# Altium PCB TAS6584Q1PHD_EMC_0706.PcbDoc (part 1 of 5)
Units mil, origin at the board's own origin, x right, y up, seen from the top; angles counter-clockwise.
Board outline 7086.61 x 5118.11 mil, 6 copper layers (Top Layer, GND02, SIG03, SIG04, GND05, Bottom Layer), stack 60.484 mil thick; 461 components, 247 nets, 1337 pads, 1658 vias.
Unrouted connection lines stored in the file: 67.
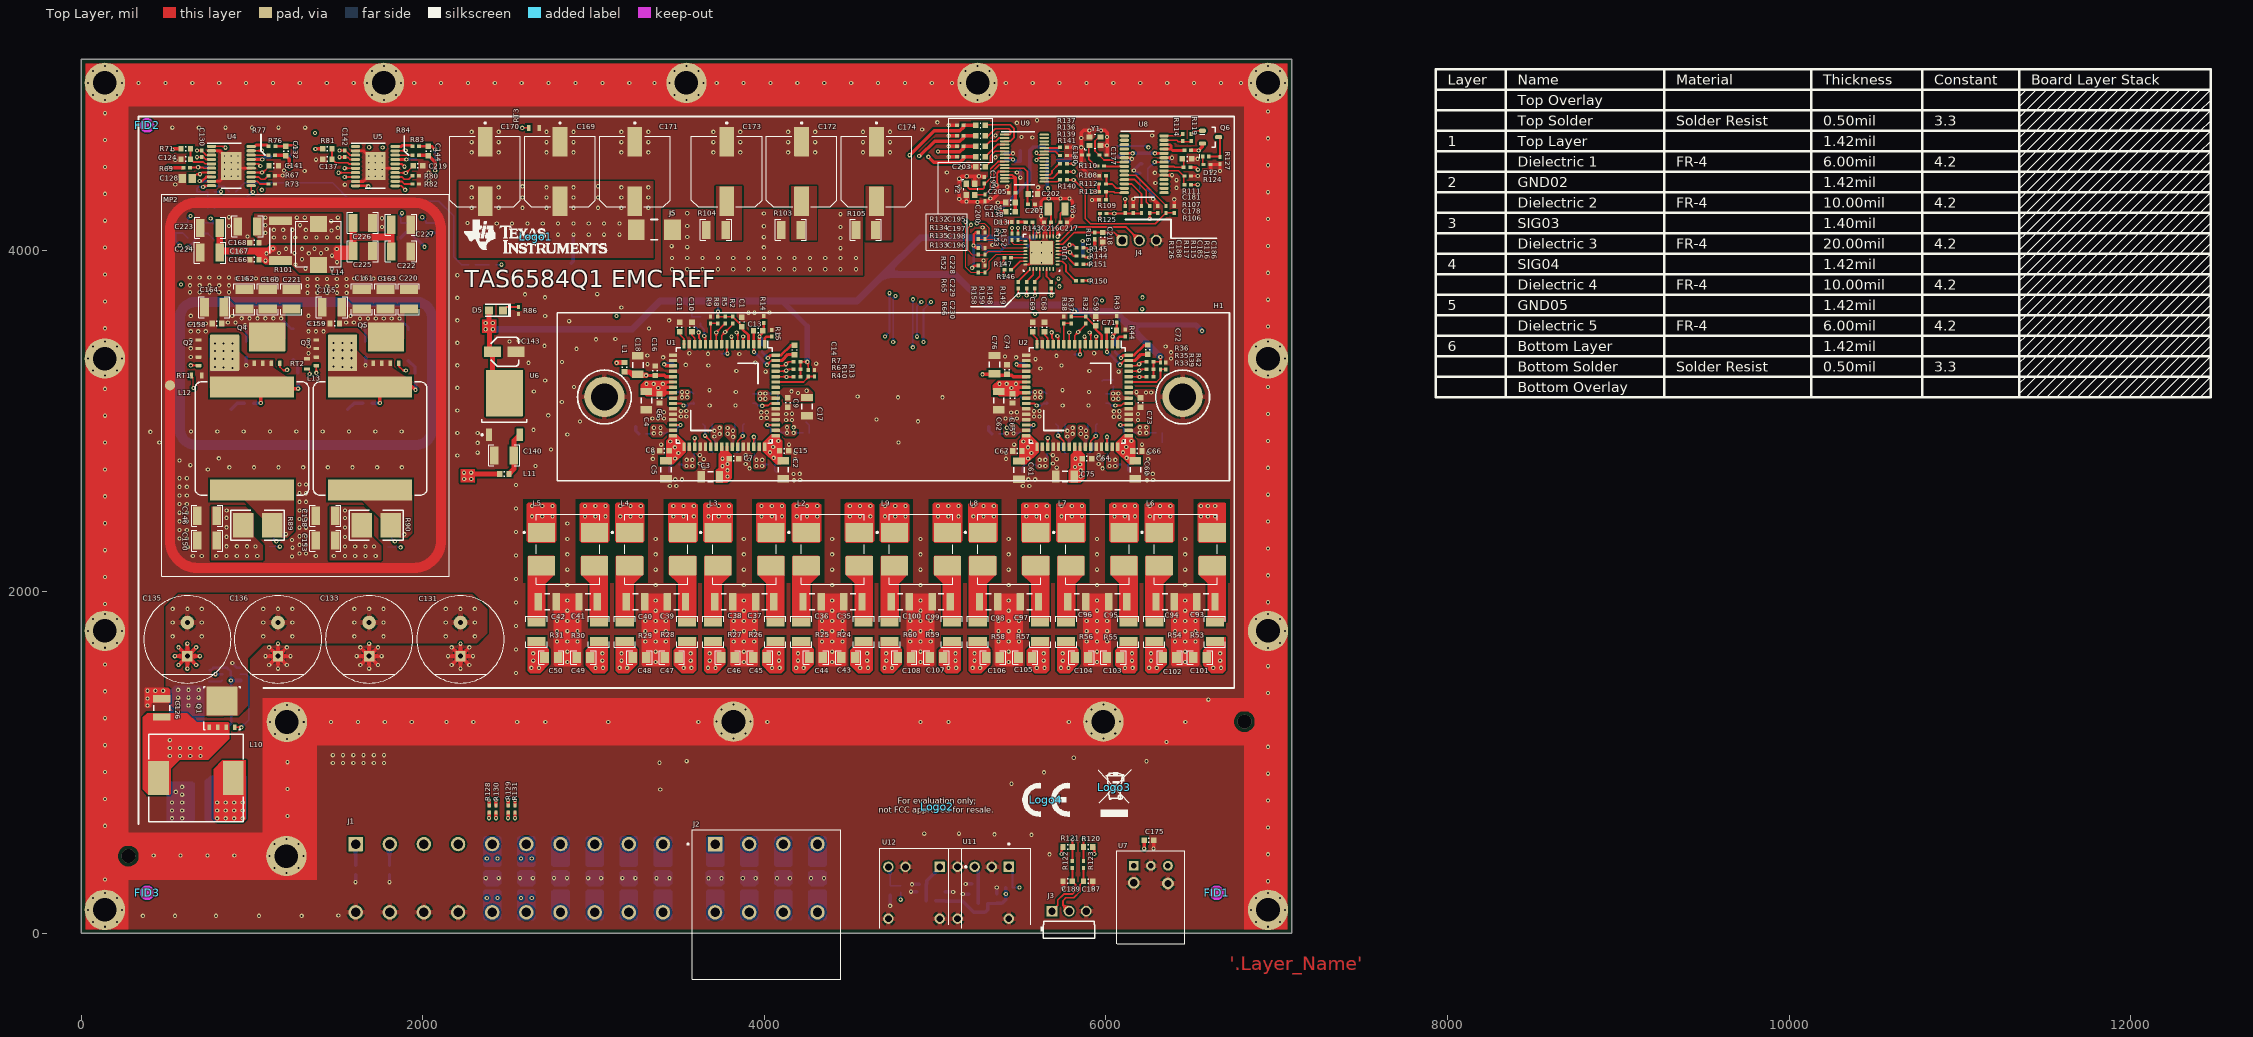
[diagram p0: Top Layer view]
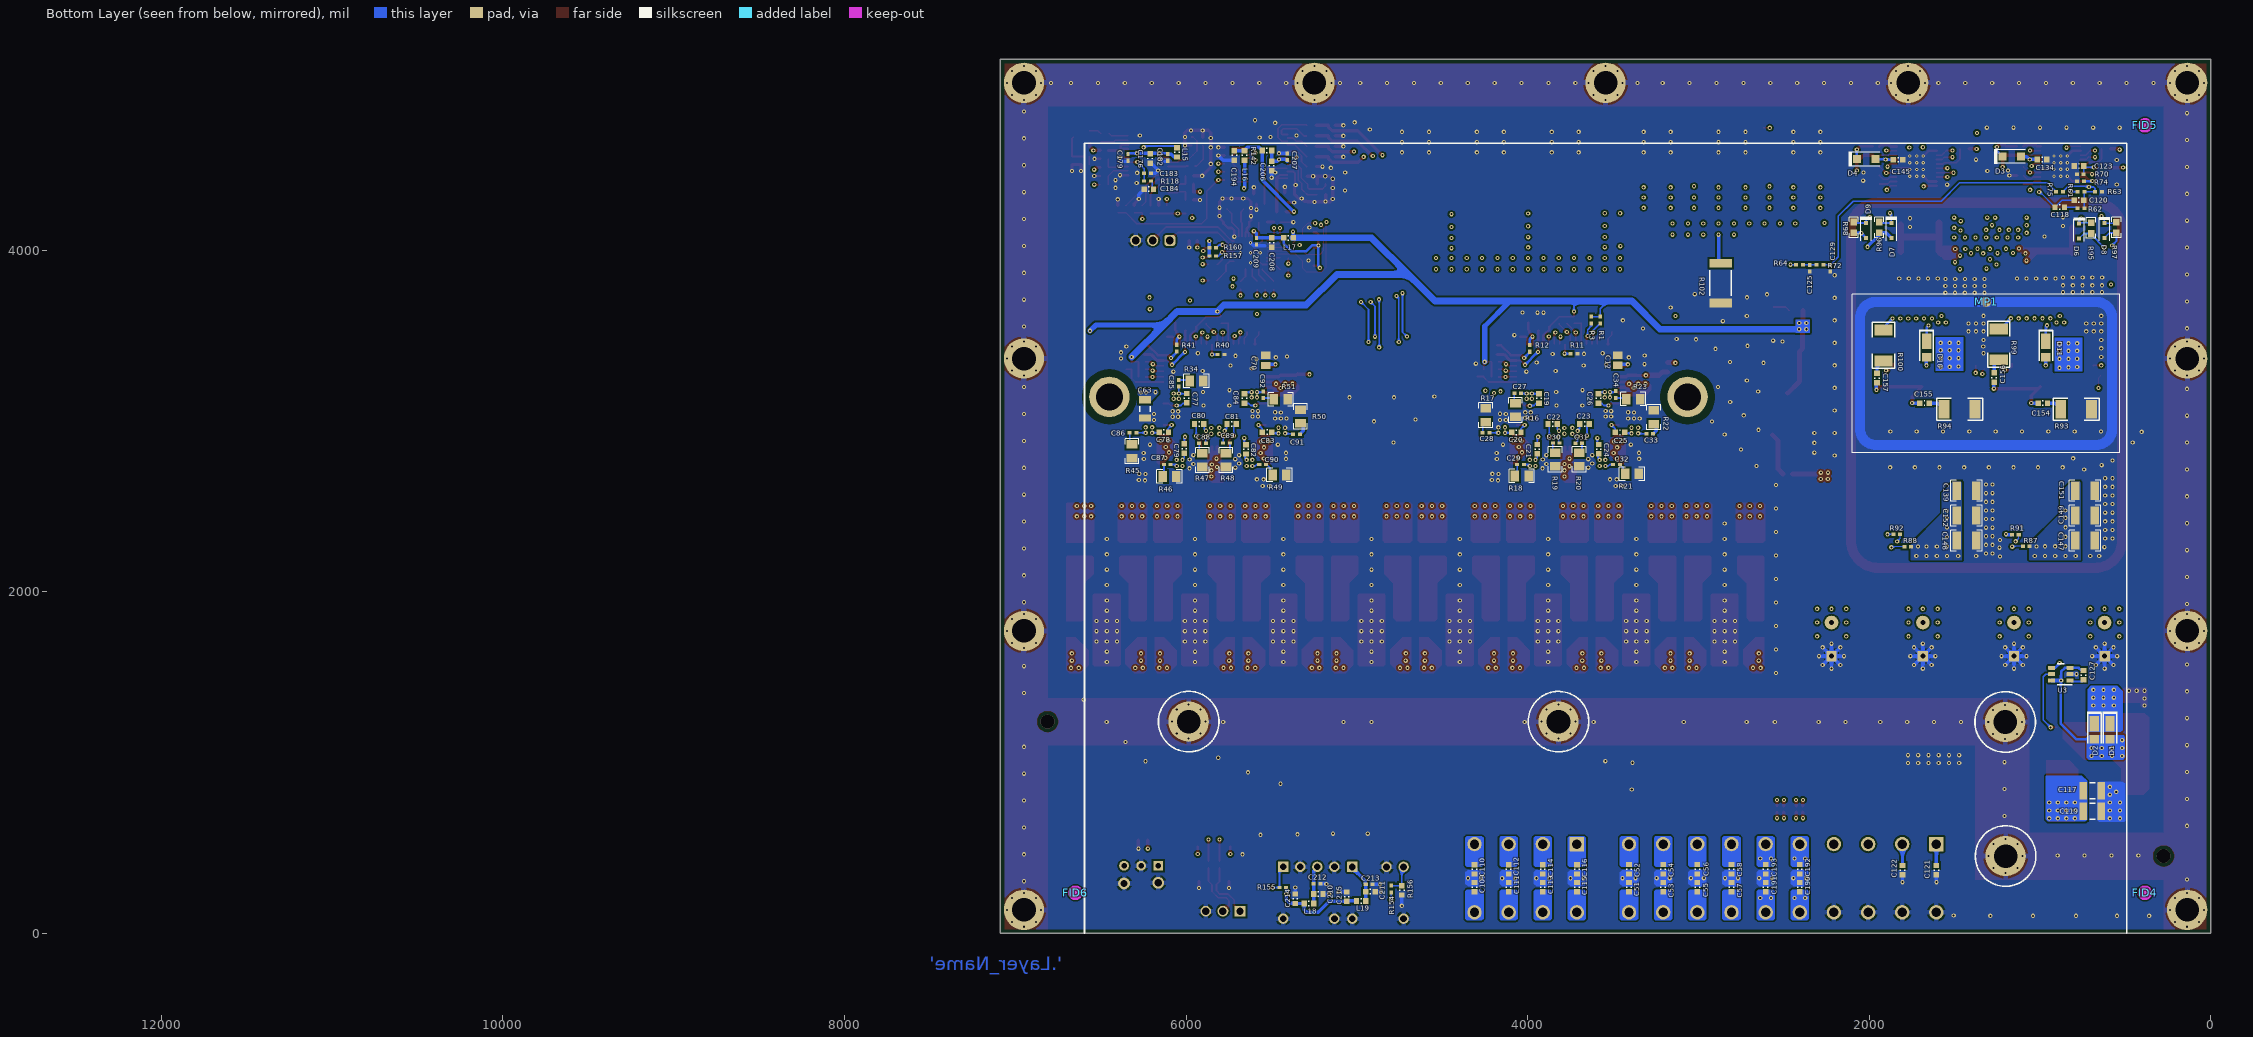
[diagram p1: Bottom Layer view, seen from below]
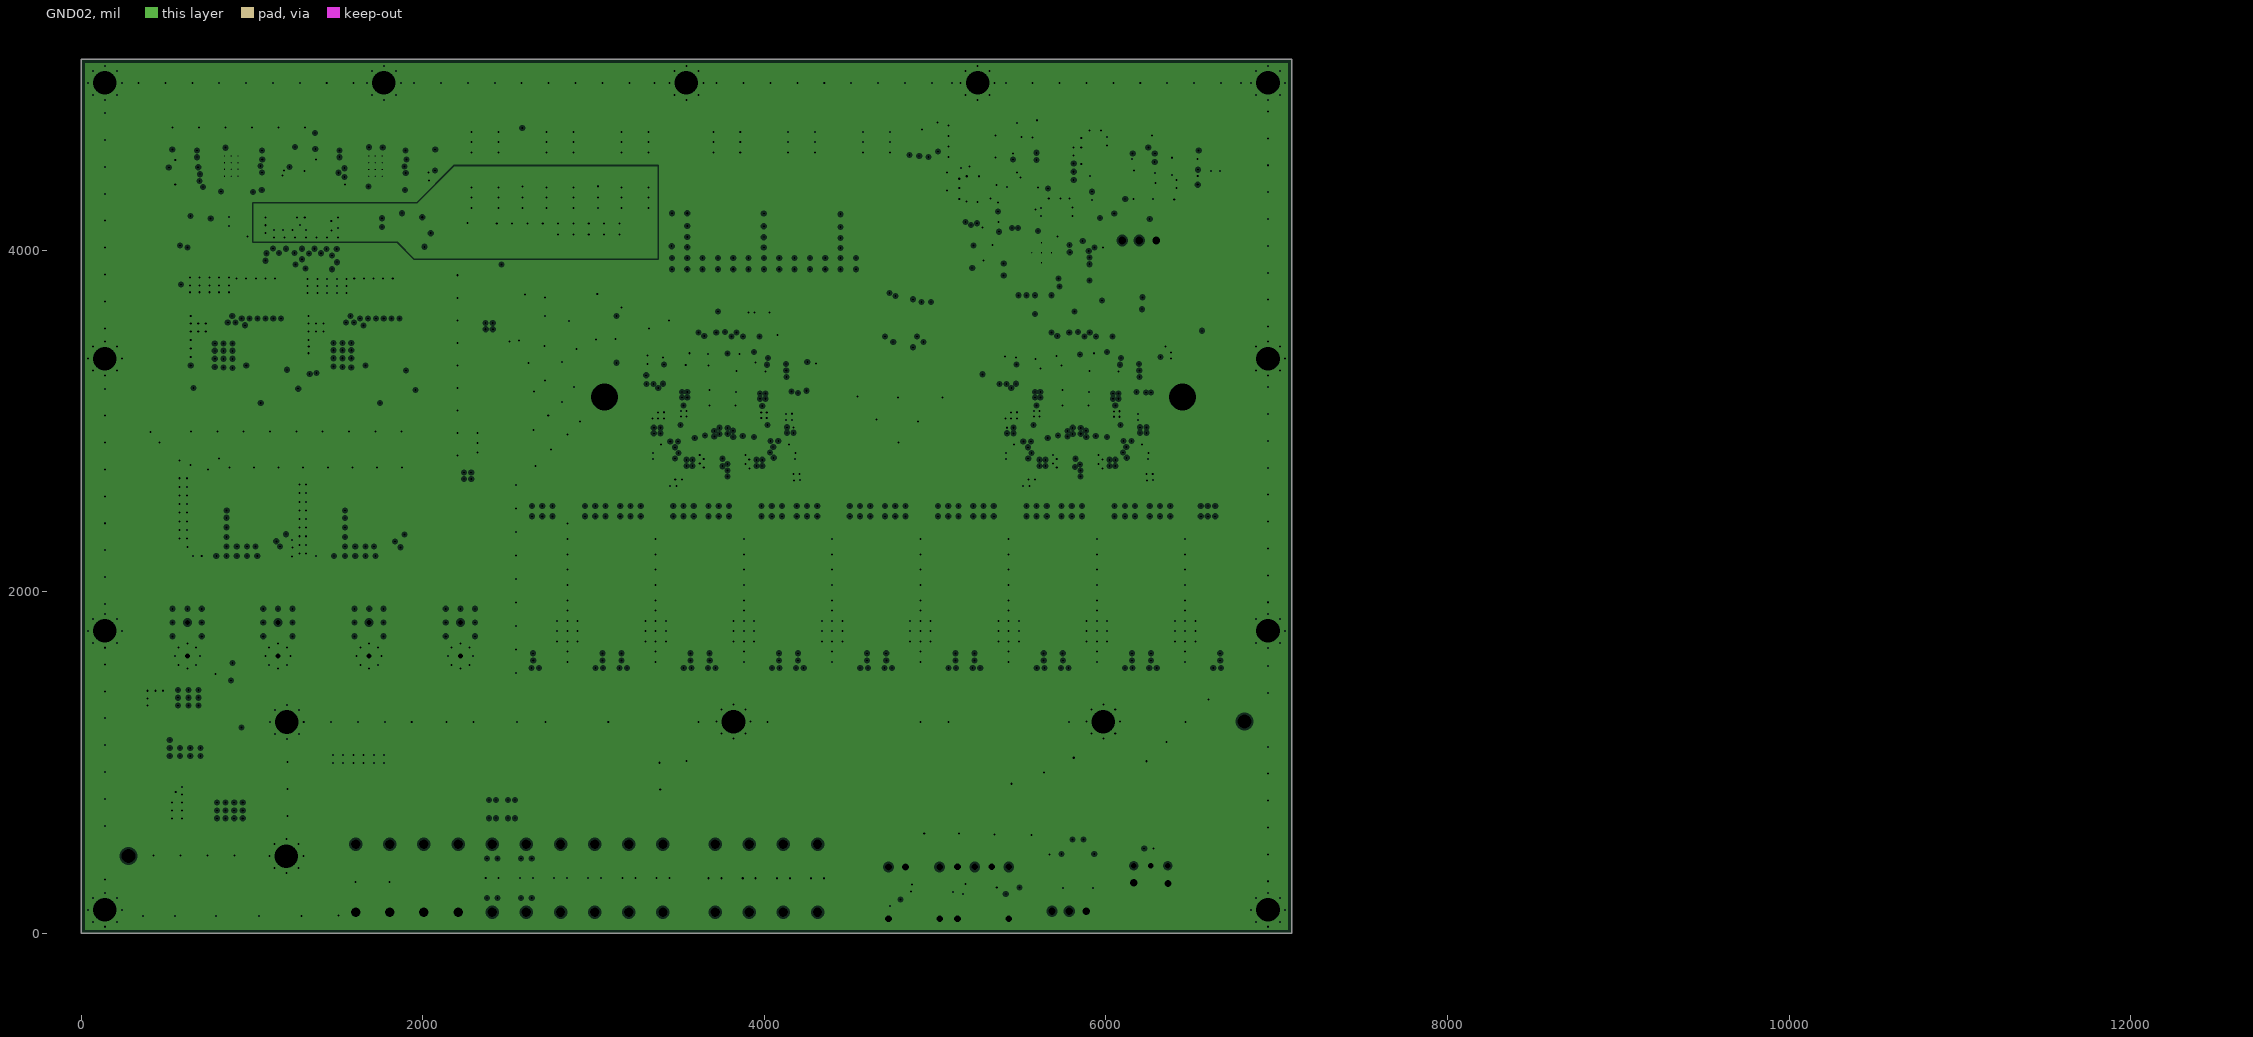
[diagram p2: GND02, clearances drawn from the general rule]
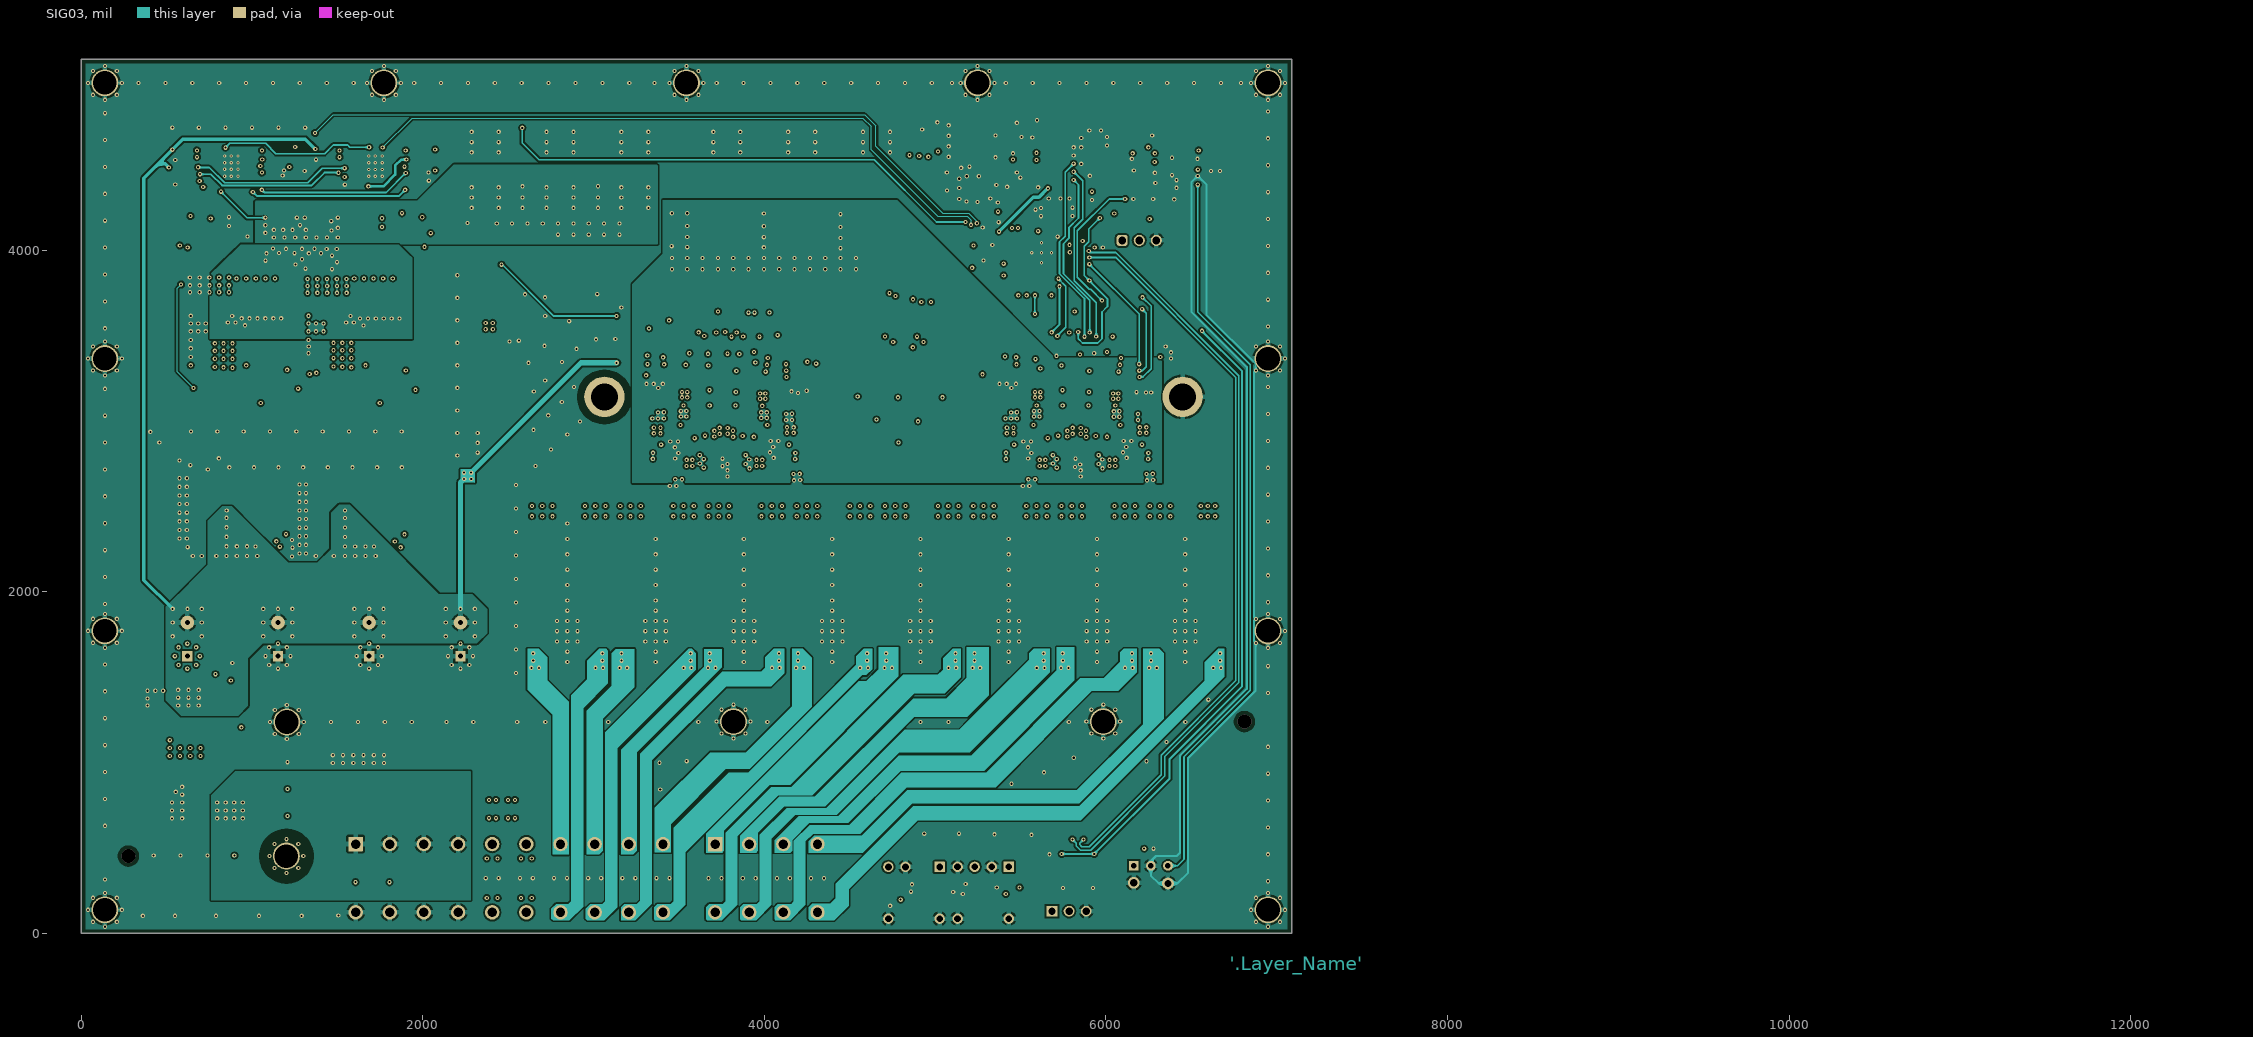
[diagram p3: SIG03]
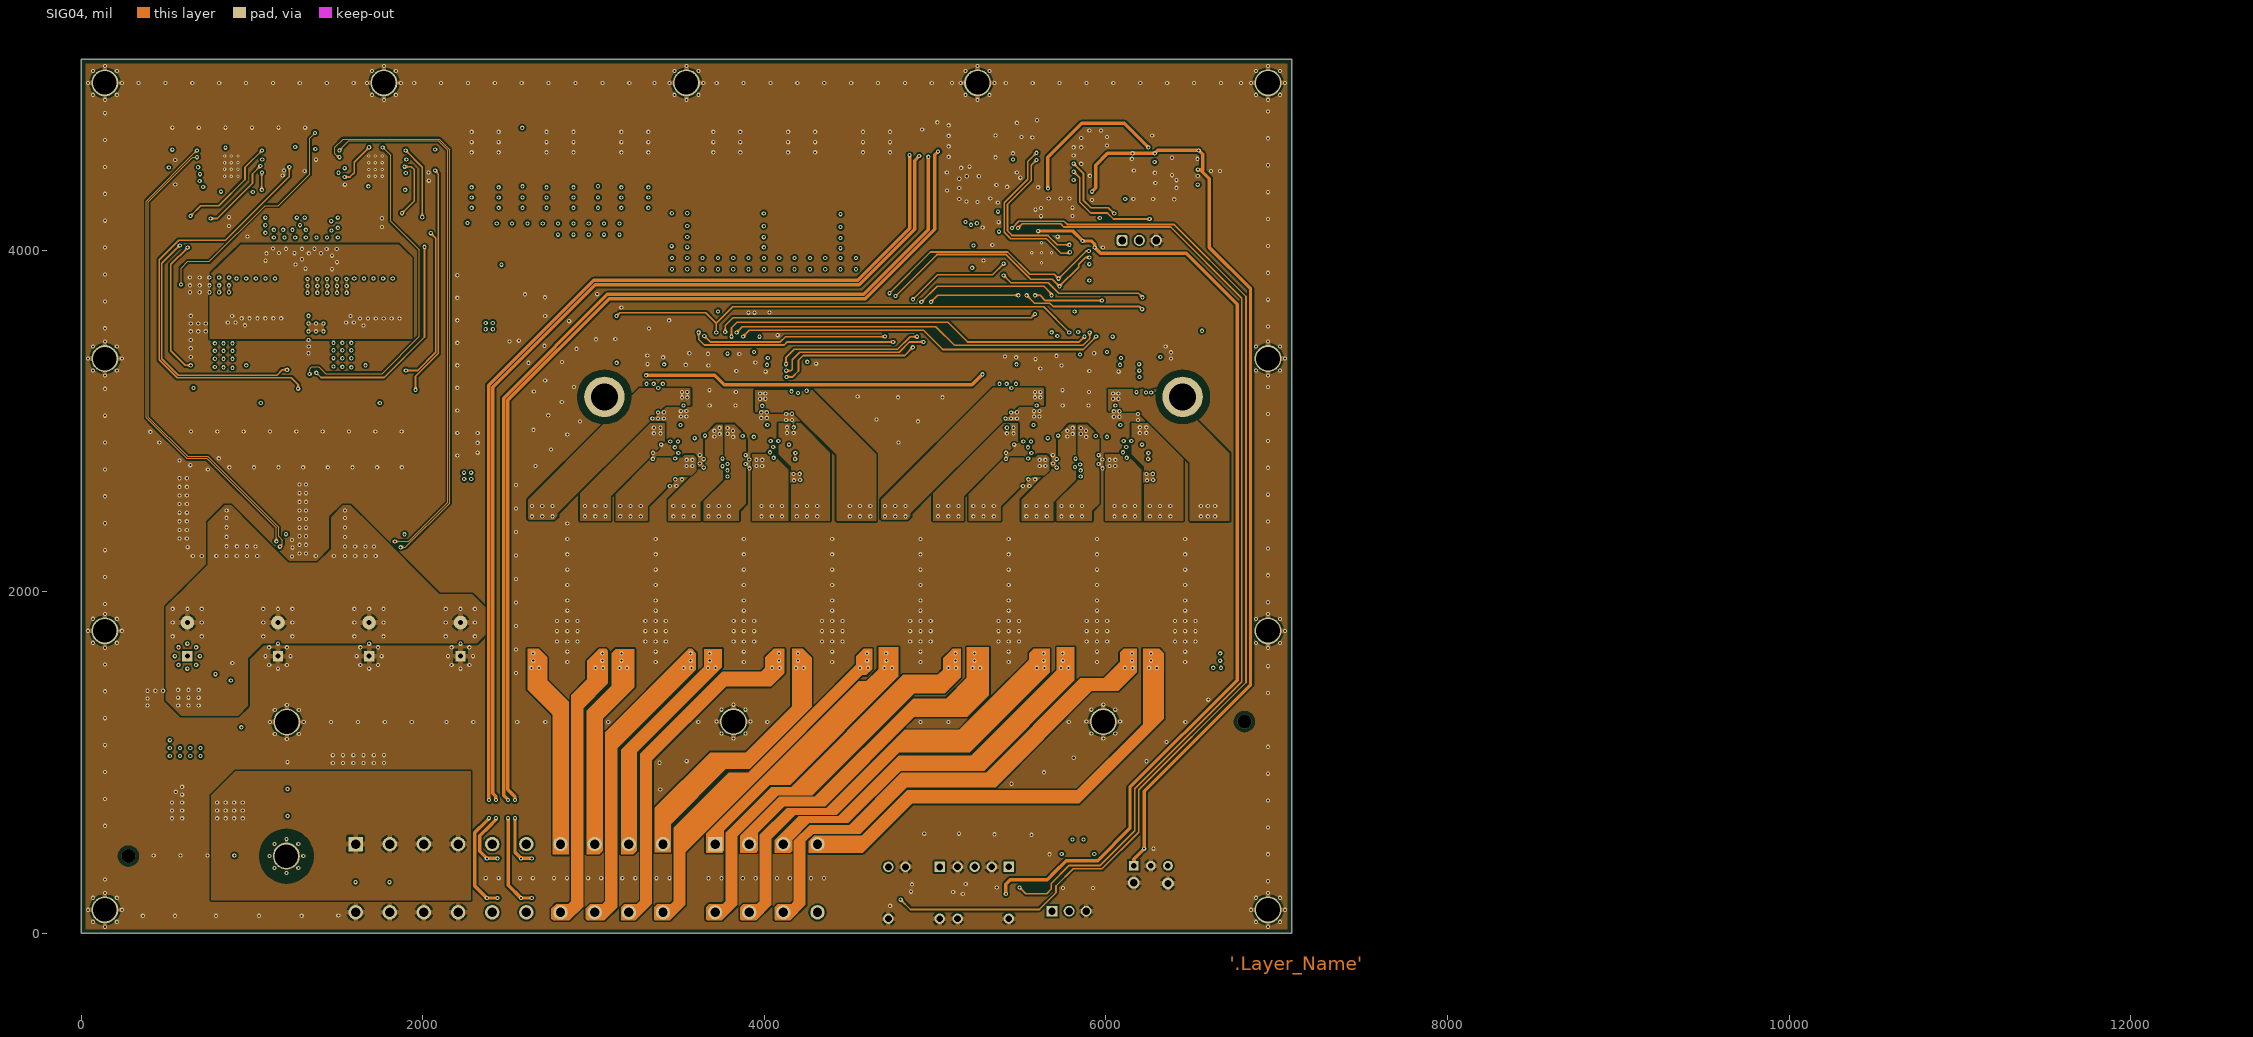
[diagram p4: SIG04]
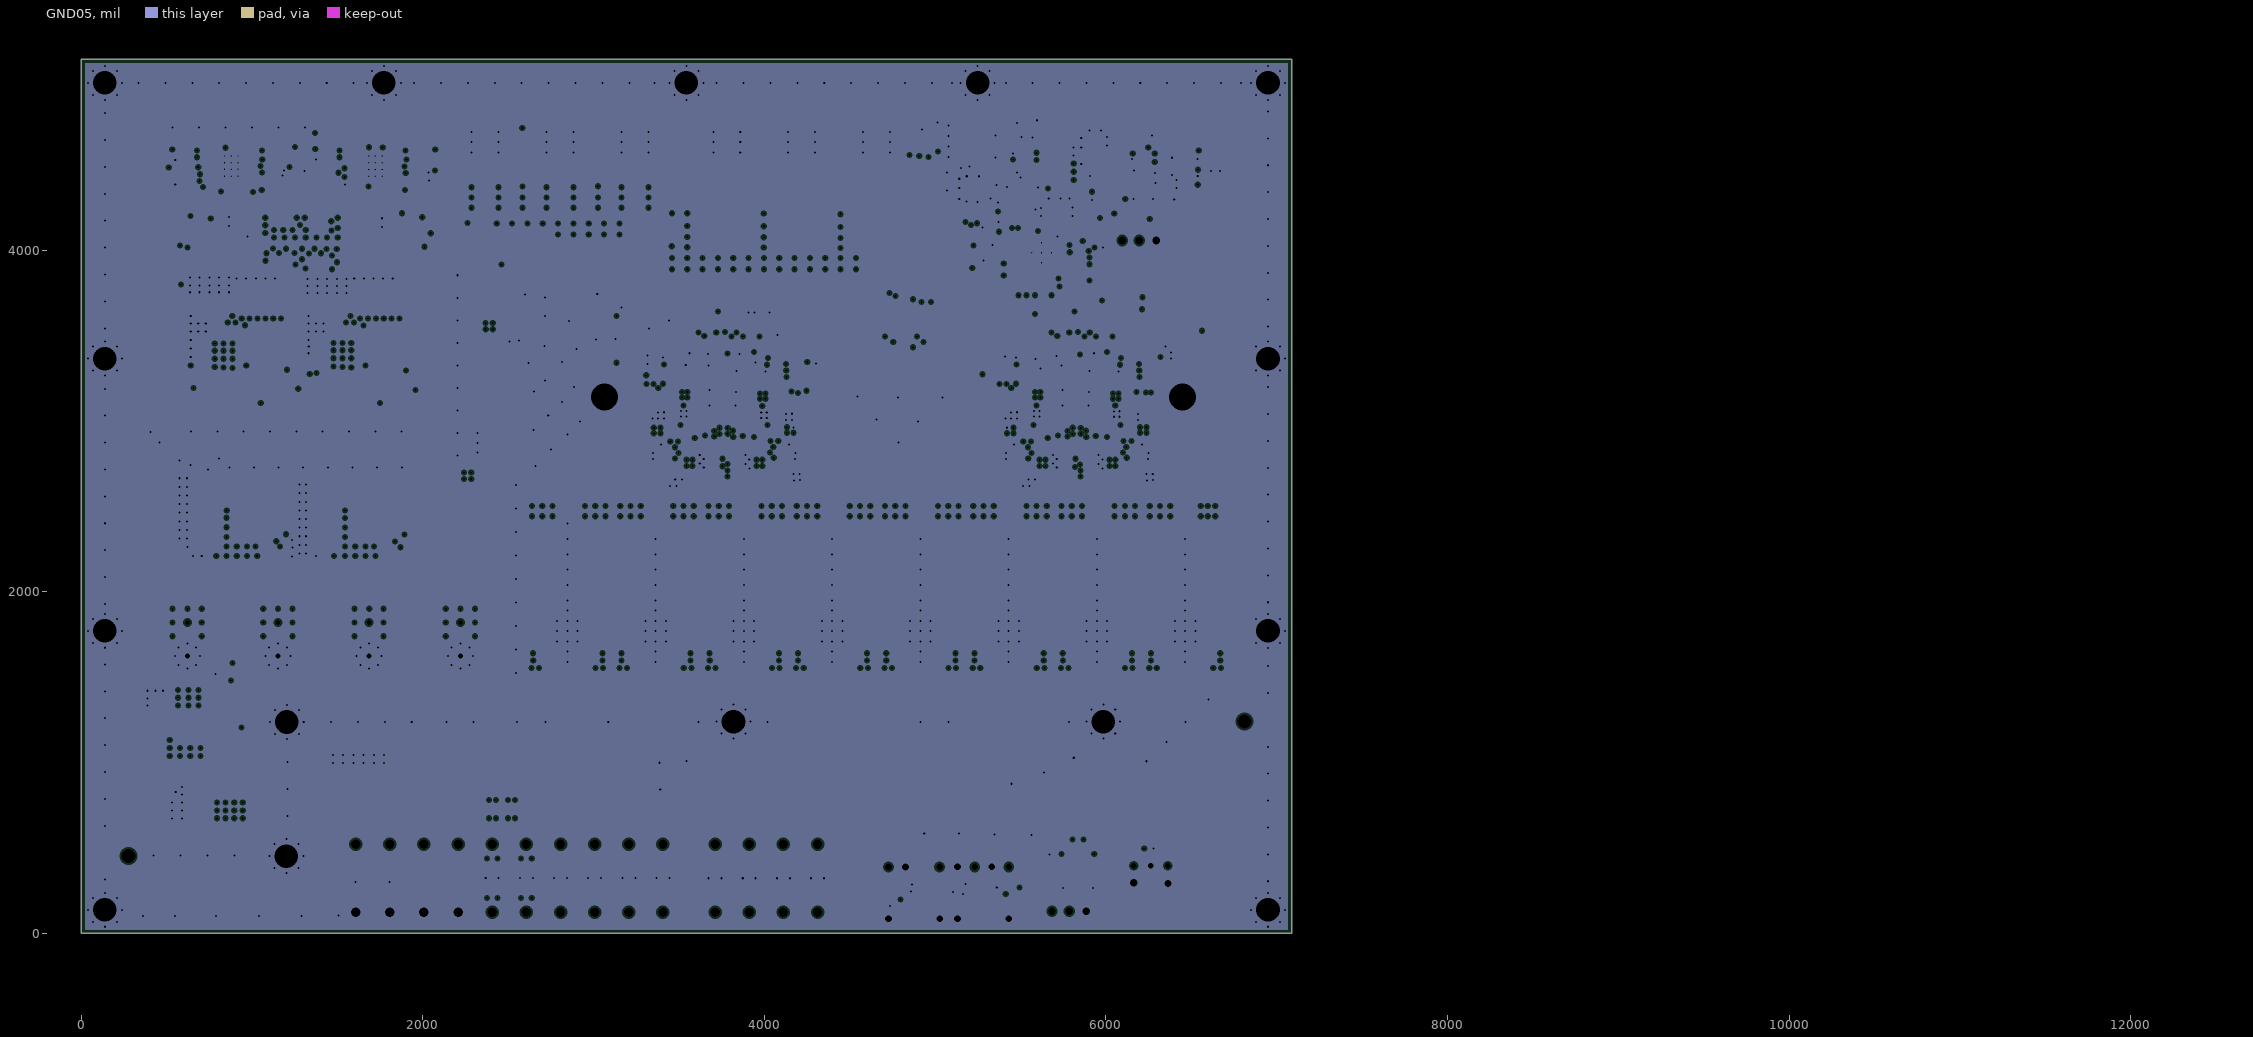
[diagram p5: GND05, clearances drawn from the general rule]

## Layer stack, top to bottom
Top Solder: solder mask 0.5, Solder Resist, Dk 3.3
Top Layer: signal copper 1.4169
Dielectric 1: prepreg 6, FR-4, Dk 4.2
GND02: plane copper 1.4169, net (Multiple Nets)
Dielectric 2: prepreg 10, FR-4, Dk 4.2
SIG03: signal copper 1.4
Dielectric 3: core 20, FR-4, Dk 4.2
SIG04: signal copper 1.4169
Dielectric 4: prepreg 10, FR-4, Dk 4.2
GND05: plane copper 1.4169, net GND
Dielectric 5: prepreg 6, FR-4, Dk 4.2
Bottom Layer: signal copper 1.4169
Bottom Solder: solder mask 0.5, Solder Resist, Dk 3.3

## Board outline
0,0 7086.61,0 7086.61,5118.11 0,5118.11

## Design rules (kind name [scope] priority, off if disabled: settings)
AcuteAngle [All] p1 off: minimum=4.50000000000000E+0001 checktracksonly=FALSE
AssemblyTestPointUsage [All] p1 off: valid=2
AssemblyTestpoint [All] p1 off: testpointundercomponent=TRUE minsize=40 maxsize=100 preferedsize=60 minholesize=0 maxholesize=40 preferedholesize=32 testpointgrid=1 usegrid=TRUE gridtolerance=0.01 allowsidetop=TRUE allowsidebottom=TRUE
Clearance Clearance_FID [InComponent('FID*')] p1: gap=7.87 ignorepadtopadclearanceinfootprint=TRUE except(0: Arc-SMDPad Arc-Hole Track-SMDPad Track-Hole SMDPad-Hole THPad-Hole Via-Hole Fill-Hole Poly-Hole Region-Hole Text-Hole; 20: Fill-Fill Fill-Poly Fill-Region Poly-Poly Poly-Region Region-Region)
Clearance [All] p2: gap=10 ignorepadtopadclearanceinfootprint=TRUE except(0: Arc-Text Arc-Hole Track-Text Track-Hole SMDPad-Text SMDPad-Hole THPad-Text THPad-Hole Via-Text Via-Hole Fill-Text Fill-Hole Poly-Text Poly-Hole Region-Text Region-Hole Text-Text Text-Hole; 5: Arc-Arc Arc-Track Track-Track; 7: Arc-SMDPad Arc-THPad Arc-Via Track-SMDPad Track-THPad Track-Via SMDPad-SMDPad SMDPad-THPad SMDPad-Via THPad-THPad THPad-Via Via-Via)
ComponentClearance ComponentClearance_1 [InComponent('H1')] p1: gap=-1000 collisioncheckmode=3 verticalgap=100000 showdistances=FALSE
ComponentClearance ComponentClearance_MountingHoles_FiducialMarks [InComponentClass('Mounting Holes') vs InComponentClass('FiducialMark')] p2: gap=50 collisioncheckmode=3 verticalgap=10 showdistances=FALSE
ComponentClearance ComponentClearance_Shunt [InComponentClass('Header') vs InComponentClass('Shunt')] p3: gap=0 collisioncheckmode=3 verticalgap=0 showdistances=FALSE
ComponentClearance ComponentClearance_Logo [InComponentClass('Logo')] p4: gap=50 collisioncheckmode=3 verticalgap=100000 showdistances=FALSE
ComponentClearance ComponentClearance_ScrewToNut [(HasFootprint('NY PMS 440 0025 PH')) vs (HasFootprint('Keystone_1902C'))] p5: gap=5 collisioncheckmode=3 verticalgap=10 showdistances=FALSE
ComponentClearance ComponentClearance_MountingHoles [InComponentClass('Mounting Holes')] p6: gap=250 collisioncheckmode=3 verticalgap=100000 showdistances=FALSE
ComponentClearance ComponentClearance_SmallPassives [HasFootprint('0201*') or HasFootprint('0402*') or HasFootprint('0508') or HasFootprint('0603*') or HasFootprint('0612') or HasFootprint('0805*') or HasFootprint('0815*') or HasFootprint('0830*') or HasFootprint('1206*') or HasFootprint('1210*') or HasFootprint('1808*') or HasFootprint('1812*') or HasFootprint('1825*') or HasFootprint('2010*') or HasFootprint('2220*') or HasFootprint('2225*') or HasFootprint('2512*') or HasFootprint('2728*') or HasFootprint('3518*') vs HasFootprint('0201*') or HasFootprint('0402*') or HasFootprint('0508') or HasFootprint('0603*') or HasFootprint('0612') or HasFootprint('0805*') or HasFootprint('0815*') or HasFootprint('0830*') or HasFootprint('1206*') or HasFootprint('1210*') or HasFootprint('1808*') or HasFootprint('1812*') or HasFootprint('1825*') or HasFootprint('2010*') or HasFootprint('2220*') or HasFootprint('2225*') or HasFootprint('2512*') or HasFootprint('2728*') or HasFootprint('3518*')] p7: gap=14.96 collisioncheckmode=3 verticalgap=10 showdistances=FALSE
ComponentClearance ComponentClearance_THtoSMT [IsThruComponent vs IsSMTComponent] p8: gap=40 collisioncheckmode=3 verticalgap=25 showdistances=FALSE
ComponentClearance ComponentClearance_THtoTH [IsThruComponent vs IsThruComponent] p9: gap=20 collisioncheckmode=3 verticalgap=20 showdistances=FALSE
ComponentClearance [All] p10: gap=5 collisioncheckmode=3 verticalgap=5 showdistances=FALSE
DiffPairsRouting [All] p1 off: maxlimit=100 minlimit=10 mostfreqgap=10 toplayer_minwidth=15 toplayer_maxwidth=15 toplayer_prefwidth=15 midlayer3_minwidth=15 midlayer3_maxwidth=15 midlayer3_prefwidth=15 midlayer6_minwidth=15 midlayer6_maxwidth=15 midlayer6_prefwidth=15 bottomlayer_minwidth=15 bottomlayer_maxwidth=15 bottomlayer_prefwidth=15 maxuncoupledlength=1000
FabricationTestPointUsage TestPointUsage [All] p1 off: valid=2 allowmultiple=FALSE
FabricationTestpoint Testpoint [All] p1 off: side=3 testpointundercomponent=TRUE minsize=40 maxsize=100 preferedsize=60 minholesize=0 maxholesize=40 preferedholesize=32 testpointgrid=1 allowsidetop=TRUE allowsidebottom=TRUE usegrid=TRUE gridtolerance=0.01
FanoutControl Fanout_LCC [IsLCC] p1 off: bgadir=Out bgaviamode=Centered fanoutstyle=Auto fanoutdirection=Alternating viagrid=1 // Fanout_LCC (Default Rule)
FanoutControl Fanout_BGA [IsBGA] p2 off: bgadir=Out bgaviamode=Centered fanoutstyle=Auto fanoutdirection=Alternating viagrid=1 // Fanout_BGA (Default Rule)
FanoutControl Fanout_SOIC [IsSOIC] p3 off: bgadir=Out bgaviamode=Centered fanoutstyle=Auto fanoutdirection=Alternating viagrid=1 // Fanout_SOIC (Default Rule)
FanoutControl Fanout_Default [All] p4 off: bgadir=Out bgaviamode=Centered fanoutstyle=Auto fanoutdirection=Alternating viagrid=1 // Fanout_Default (Default Rule)
FanoutControl Fanout_Small [(CompPinCount < 5)] p5 off: bgadir=Out bgaviamode=Centered fanoutstyle=Auto fanoutdirection=OutThenIn viagrid=1 // Fanout_Small (Default Rule)
Height [All] p1 off: minheight=0 maxheight=1000 prefheight=500
HoleSize [All] p1 off: absolutevalues=TRUE maxlimit=251 minlimit=7.87 maxpercent=80.000 minpercent=20.000
HoleToHoleClearance [All] p1 off: gap=10 allowstackedmicrovias=TRUE
LayerPairs [All] p1 off: enforce=TRUE
MinimumAnnularRing MinimumAnnularRing_ThermalPadVias [IsVia and InAnyComponent] p1 off: minimumring=5.91
MinimumAnnularRing [All] p2 off: minimumring=7.87
MinimumSolderMaskSliver MinimumSolderMaskSliver_Logo [InComponentClass('Logo') vs InComponentClass('Logo')] p1 off: minsoldermaskwidth=0.7
MinimumSolderMaskSliver [All] p2 off: minsoldermaskwidth=3.94
PlaneClearance [All] p1: clearance=12
PlaneConnect PlaneConnect_1 [IsThruPin] p1: planeconnectstyle=Relief reliefexpansion=10 reliefentries=4 reliefconductorwidth=30 reliefairgap=12
PlaneConnect [All] p2: planeconnectstyle=Direct reliefexpansion=10 reliefentries=4 reliefconductorwidth=10 reliefairgap=10
PolygonConnect PolygonConnect_1 [IsThruPin] p1: connectstyle=Relief reliefconductorwidth=30 reliefentries=4 polygonreliefangle="90 Angle" airgapwidth=12
PolygonConnect [All] p2: connectstyle=Direct reliefconductorwidth=20 reliefentries=4 polygonreliefangle="90 Angle" airgapwidth=12
RoutingVias [All] p1: holewidth=12 width=25 viastyle="Through Hole" minholewidth=10 minwidth=20 maxholewidth=15 maxwidth=30 useviatemplates=TRUE viatemplateguid#1={6C5415AD-AB15-4F71-99E7-3C6550FFFBAB} viatemplatename#1=v64h30
SilkToBoardRegionClearance [Not ((IsComment or IsDesignator) And (Hide <> 'False')) and not InRegion(1000,500,4000,800)] p1 off:
SilkToSilkClearance SilkToSilkClearance_Pb-FreeLogo [(HasFootprint('Pb-Free_Overlay_Medium') OR HasFootprint('Pb-Free_Overlay_Small')) vs (HasFootprint('Pb-Free_Overlay_Medium') OR HasFootprint('Pb-Free_Overlay_Small'))] p1 off: silktosilkclearance=0
SilkToSilkClearance [All] p2 off: silktosilkclearance=3.94
SilkToSolderMaskClearance SilkToComponentPadClearance [(IsPad or IsFill or IsRegion) and InAnycomponent] p1 off: minsilkscreentomaskgap=5 clearancetoexposedcopper=TRUE
SilkToSolderMaskClearance "Silk to Solder Mask Opening" [All] p2 off: minsilkscreentomaskgap=3.94 clearancetoexposedcopper=FALSE
SolderMaskExpansion SolderMaskExpansion_1 [isvia] p1: expansion=-40 istentingtop=FALSE
SolderMaskExpansion [All] p2: expansion=1.97 istentingtop=FALSE
ViasUnderSMD [All] p1 off: allowed=FALSE
Width Width_1 [InNetClass('PW')] p1: maxlimit=200 minlimit=10 preferedwidth=16
Width [All] p2: maxlimit=100 minlimit=6 preferedwidth=10 checkconnectedcopper=TRUE
9 further rules are at their usual default settings.

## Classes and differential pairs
component class FiducialMark: FID1 FID2 FID3 FID4 FID5 FID6
component class TAS6584Q1PHD_2: C59 C60 C61 C62 C63 C64 C65 C66 C67 C68 C69 C70 C71 C72 C73 C74 C75 C76 C77 C78 C79 C80 C81 C82 C83 C84 C85 C86 C87 C88 C89 C90 C91 C92 C93 C94 C95 C96 C97 C98 C99 C100 C101 C102 C103 C104 C105 C106 C107 C108 C109 C110 C111 C112 C113 C114 C115 C116 L6 L7 L8 L9 R32 R33 R34 R35 R36 R37 R38 R39 R40 R41 R42 R43 R44 R45 R46 R47 R48 R49 R50 R51 R53 R54 R55 R56 R57 R58 R59 R60 U2
component class TAS6584Q1PHD_1: C1 C2 C3 C4 C5 C6 C7 C8 C9 C10 C11 C12 C13 C14 C15 C16 C17 C18 C19 C20 C21 C22 C23 C24 C25 C26 C27 C28 C29 C30 C31 C32 C33 C34 C35 C36 C37 C38 C39 C40 C41 C42 C43 C44 C45 C46 C47 C48 C49 C50 C51 C52 C53 C54 C55 C56 C57 C58 H1 L1 L2 L3 L4 L5 R1 R2 R3 R4 R5 R6 R7 R8 R9 R10 R11 R12 R13 R14 R15 R16 R17 R18 R19 R20 R21 R22 R23 R24 R25 R26 R27 R28 R29 R30 R31 U1
component class "SPDIF and Interface": C175 C176 C177 C178 C179 C180 C181 C182 C183 C184 C185 C186 C187 C188 C189 D12 FID1 FID2 FID3 FID4 FID5 FID6 J1 J2 J3 L15 Logo1 Logo2 Logo3 Logo4 Q6 R106 R107 R108 R109 R110 R111 R112 R113 R114 R115 R116 R117 R118 R119 R120 R121 R122 R123 R124 R125 R126 R127 U7 U8 Y1
component class PowerSupplies_Powerstage: C146 C147 C148 C149 C150 C151 C152 C153 C154 C155 C156 C157 C158 C159 C160 C161 C162 C163 C164 C165 C166 C167 C168 C169 C170 C171 C172 C173 C174 C220 C221 C222 C223 C224 C225 C226 C227 D6 D7 D8 D9 D10 D11 J5 L12 L13 L14 MP1 MP2 Q2 Q3 Q4 Q5 R87 R88 R89 R90 R91 R92 R93 R94 R95 R96 R97 R98 R99 R100 R101 R102 R103 R104 R105
component class PowerSupplies_Boostcontroller: C117 C118 C119 C120 C121 C122 C123 C124 C125 C126 C127 C128 C129 C130 C131 C132 C133 C134 C135 C136 C137 C138 C139 C140 C141 C142 C143 C144 C145 C219 D1 D2 D3 D4 D5 L10 L11 Q1 R61 R62 R63 R64 R67 R69 R70 R71 R72 R73 R74 R75 R76 R77 R80 R81 R82 R83 R84 R86 U3 U4 U5 U6
component class MCU: C208 C209 C210 C211 C212 C213 C214 C215 C216 C217 C218 C228 C229 C230 D13 J4 L17 L18 L19 R52 R65 R66 R143 R144 R145 R146 R147 R148 R149 R150 R151 R152 R153 R154 R155 R156 R157 R158 R159 R160 R161 RT1 RT2 RT3 U10 U11 U12 Y3
component class Header: J3 J4
component class "GND Thermals 0.5mm": C117 C119 C126
component class ADC: C190 C191 C192 C193 C194 C195 C196 C197 C198 C199 C200 C201 C202 C203 C204 C205 C206 C207 L16 R128 R129 R130 R131 R132 R133 R134 R135 R136 R137 R138 R139 R140 R141 R142 U9 Y2
component class Logo: Logo1

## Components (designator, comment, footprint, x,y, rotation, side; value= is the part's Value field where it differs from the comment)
C1 "GCM188R71E105KA64D" 0603L 3867.8,3580.01 r90 top value=1uF
C2 "GCJ31CR72A105KA01K" 1206L 4110,2715 r270 top value=1uF
C3 "GCJ31CR72A105KA01K" 1206L 3684,2674 r180 top value=1uF
C4 "GCJ31CR72A105KA01K" 1206L 3308.39,3120.2 r270 top value=1uF
C5 "GCJ31CR72A105KA01K" 1206L 3423,2715 r270 top value=1uF
C6 "GCJ188R72A104KA01D" 0603L 3385.71,3133.12 r270 top value=0.1uF
C7 "GCJ188R72A104KA01D" 0603L 3821.25,2780 r0 top value=0.1uF
C8 "GCJ188R72A104KA01D" 0603L 3414.3,2826 r180 top value=0.1uF
C9 "GCJ188R72A104KA01D" 0603L 4137,3108 r270 top value=0.1uF
C10 "GCM188R71E105KA64D" 0603L 3575.75,3550 r270 top value=1uF
C11 "GCM188R71E105KA64D" 0603L 3503.33,3550 r270 top value=1uF
C12 "GCM21BR71E225KA73L" 0805L 3472.78,3355.72 r90 bottom value=2.2uF
C13 "GCM188R71E105KA64D" 0603L 3963.45,3529.32 r180 top value=1uF
C14 "GCM188R71E105KA64D" 0603L 4176.23,3416.22 r270 top value=1uF
C15 "GCJ188R72A104KA01D" 0603L 4115.56,2825.5 r0 top value=0.1uF
C16 "GCJ188R72A104KA01D" 0603L 3360,3294.56 r90 top value=0.1uF
C17 "GCJ31CR72A105KA01K" 1206L 4249,3085 r270 top value=1uF
C18 "GCJ31CR72A105KA01K" 1206L 3258.73,3328.15 r90 top value=1uF
C19 "GCM188R71H224KA64D" 0603L 3932.8,3132.28 r270 bottom value=0.22uF
C20 "GCM188R71H224KA64D" 0603L 4066,2933.88 r180 bottom value=0.22uF
C21 "GCM188R71H224KA64D" 0603L 3943.44,2835.21 r90 bottom value=0.22uF
C22 "GCM188R71H224KA64D" 0603L 3853.08,2982.99 r0 bottom value=0.22uF
C23 "GCM188R71H224KA64D" 0603L 3666.43,2982.99 r180 bottom value=0.22uF
C24 "GCM188R71H224KA64D" 0603L 3582.83,2835.21 r90 bottom value=0.22uF
C25 "GCM188R71H224KA64D" 0603L 3458.76,2933.88 r0 bottom value=0.22uF
C26 "GCM188R71H224KA64D" 0603L 3585.06,3132.28 r270 bottom value=0.22uF
C27 "GRM155R72A331KA01D" 0402L 4057.83,3163.17 r180 bottom value=330pF
C28 "GRM155R72A331KA01D" 0402L 4243.5,2930.57 r180 bottom value=330pF
C29 "GRM155R72A331KA01D" 0402L 4041.58,2745.57 r180 bottom value=330pF
C30 "GRM155R72A331KA01D" 0402L 3832.33,2871.39 r180 bottom value=330pF
C31 "GRM155R72A331KA01D" 0402L 3700.42,2870.43 r0 bottom value=330pF
C32 "GRM155R72A331KA01D" 0402L 3479.71,2745.57 r0 bottom value=330pF
C33 "GRM155R72A331KA01D" 0402L 3284.66,2925.97 r0 bottom value=330pF
C34 "GRM155R72A331KA01D" 0402L 3483.31,3155.01 r90 bottom value=330pF
C35 "GRM32ER72A225KA35L" 1210_270L 4518.07,1941.66 r180 top value=2.2uF
C36 "GRM32ER72A225KA35L" 1210_270L 4278.74,1941.66 r0 top value=2.2uF
C37 "GRM32ER72A225KA35L" 1210_270L 4001.23,1941.66 r180 top value=2.2uF
C38 "GRM32ER72A225KA35L" 1210_270L 3761.9,1941.66 r0 top value=2.2uF
C39 "GRM32ER72A225KA35L" 1210_270L 3484.39,1941.66 r180 top value=2.2uF
C40 "GRM32ER72A225KA35L" 1210_270L 3245.06,1941.66 r0 top value=2.2uF
C41 "GRM32ER72A225KA35L" 1210_270L 2967.55,1941.66 r180 top value=2.2uF
C42 "GRM32ER72A225KA35L" 1210_270L 2728.22,1941.66 r0 top value=2.2uF
C43 "DNP" 0805_HV 4490.88,1615.95 r180 top value=0.47uF
C44 "DNP" 0805_HV 4302.6,1615.95 r0 top value=0.47uF
C45 "DNP" 0805_HV 3974.04,1615.95 r180 top value=0.47uF
C46 "DNP" 0805_HV 3785.76,1615.95 r0 top value=0.47uF
C47 "DNP" 0805_HV 3457.21,1615.95 r180 top value=0.47uF
C48 "DNP" 0805_HV 3268.92,1615.95 r0 top value=0.47uF
C49 "DNP" 0805_HV 2940.37,1615.95 r180 top value=0.47uF
C50 "DNP" 0805_HV 2752.08,1615.95 r0 top value=0.47uF
C51 "GRM1885C1H103JA01D" 0603L 3406,270.56 r90 bottom value=0.01uF
C52 "GRM1885C1H103JA01D" 0603L 3406,375.44 r270 bottom value=0.01uF
C53 "GRM1885C1H103JA01D" 0603L 3206,270.56 r90 bottom value=0.01uF
C54 "GRM1885C1H103JA01D" 0603L 3206,375.44 r270 bottom value=0.01uF
C55 "GRM1885C1H103JA01D" 0603L 3006,270.56 r90 bottom value=0.01uF
C56 "GRM1885C1H103JA01D" 0603L 3006,375.44 r270 bottom value=0.01uF
C57 "GRM1885C1H103JA01D" 0603L 2806,270.56 r90 bottom value=0.01uF
C58 "GRM1885C1H103JA01D" 0603L 2806,375.44 r270 bottom value=0.01uF
C59 "GCM188R71E105KA64D" 0603L 5940.15,3586.79 r90 top value=1uF
C60 "GCJ31CR72A105KA01K" 1206L 6172,2715 r270 top value=1uF
C61 "GCJ31CR72A105KA01K" 1206L 5490.82,2713 r270 top value=1uF
C62 "GCJ31CR72A105KA01K" 1206L 5372,3120.2 r270 top value=1uF
C63 "GCJ31CR72A105KA01K" 1206L 6240.47,3071.08 r270 bottom value=1uF
C64 "GCJ188R72A104KA01D" 0603L 5888.77,2780 r0 top value=0.1uF
C65 "GCJ188R72A104KA01D" 0603L 5453.06,3133.11 r270 top value=0.1uF
C66 "GCJ188R72A104KA01D" 0603L 6183.58,2825 r0 top value=0.1uF
C67 "GCJ188R72A104KA01D" 0603L 5480.98,2825 r180 top value=0.1uF
C68 "GCM188R71E105KA64D" 0603L 5640.05,3550 r270 top value=1uF
C69 "GCM188R71E105KA64D" 0603L 5571.29,3550 r270 top value=1uF
C70 "GCM21BR71E225KA73L" 0805L 5532.16,3354.72 r90 bottom value=2.2uF
C71 "GCM188R71E105KA64D" 0603L 6034.15,3530.82 r180 top value=1uF
C72 "GCM188R71E105KA64D" 0603L 6245.04,3417.71 r270 top value=1uF
C73 "GCJ188R72A104KA01D" 0603L 6202.36,3108.36 r270 top value=0.1uF
C74 "GCJ188R72A104KA01D" 0603L 5420.45,3301.51 r90 top value=0.1uF
C75 "GCJ31CR72A105KA01K" 1206L 5760,2675 r180 top value=1uF
C76 "GCJ31CR72A105KA01K" 1206L 5346.95,3330.7 r90 top value=1uF
C77 "GCM188R71H224KA64D" 0603L 5996.56,3134.08 r270 bottom value=0.22uF
C78 "GCM188R71H224KA64D" 0603L 6130.2,2935.29 r180 bottom value=0.22uF
C79 "GCM188R71H224KA64D" 0603L 6010.8,2838.58 r90 bottom value=0.22uF
C80 "GCM188R71H224KA64D" 0603L 5922.72,2982.99 r0 bottom value=0.22uF
C81 "GCM188R71H224KA64D" 0603L 5732.89,2982.65 r180 bottom value=0.22uF
C82 "GCM188R71H224KA64D" 0603L 5649.44,2834.42 r90 bottom value=0.22uF
C83 "GCM188R71H224KA64D" 0603L 5525.04,2935.13 r0 bottom value=0.22uF
C84 "GCM188R71H224KA64D" 0603L 5657.84,3132.28 r270 bottom value=0.22uF
C85 "GRM155R72A331KA01D" 0402L 6041.81,3221.16 r270 bottom value=330pF
C86 "GRM155R72A331KA01D" 0402L 6310.44,2930.57 r180 bottom value=330pF
C87 "GRM155R72A331KA01D" 0402L 6110.52,2745.57 r180 bottom value=330pF
C88 "GRM155R72A331KA01D" 0402L 5903.47,2870.1 r180 bottom value=330pF
C89 "GRM155R72A331KA01D" 0402L 5762.64,2871.4 r0 bottom value=330pF
C90 "GRM155R72A331KA01D" 0402L 5551.6,2745.57 r0 bottom value=330pF
C91 "GRM155R72A331KA01D" 0402L 5353.24,2923 r0 bottom value=330pF
C92 "GRM155R72A331KA01D" 0402L 5548.41,3153.76 r90 bottom value=330pF
C93 "GRM32ER72A225KA35L" 1210_270L 6585.42,1941.66 r180 top value=2.2uF
C94 "GRM32ER72A225KA35L" 1210_270L 6346.09,1941.66 r0 top value=2.2uF
C95 "GRM32ER72A225KA35L" 1210_270L 6068.59,1941.66 r180 top value=2.2uF
C96 "GRM32ER72A225KA35L" 1210_270L 5829.25,1941.66 r0 top value=2.2uF
C97 "GRM32ER72A225KA35L" 1210_270L 5551.75,1941.66 r180 top value=2.2uF
C98 "GRM32ER72A225KA35L" 1210_270L 5312.42,1941.66 r0 top value=2.2uF
C99 "GRM32ER72A225KA35L" 1210_270L 5034.91,1941.66 r180 top value=2.2uF
C100 "GRM32ER72A225KA35L" 1210_270L 4795.58,1941.66 r0 top value=2.2uF
C101 "DNP" 0805_HV 6551.4,1615.95 r180 top value=0.47uF
C102 "DNP" 0805_HV 6373.12,1615.95 r0 top value=0.47uF
C103 "DNP" 0805_HV 6044.56,1615.95 r180 top value=0.47uF
C104 "DNP" 0805_HV 5856.28,1615.95 r0 top value=0.47uF
C105 "DNP" 0805_HV 5527.72,1615.95 r180 top value=0.47uF
C106 "DNP" 0805_HV 5339.18,1615.95 r0 top value=0.47uF
C107 "DNP" 0805_HV 5008.16,1615.95 r180 top value=0.47uF
C108 "DNP" 0805_HV 4819.44,1615.95 r0 top value=0.47uF
C109 "GRM1885C1H103JA01D" 0603L 4311,270.2 r90 bottom value=0.01uF
C110 "GRM1885C1H103JA01D" 0603L 4311,375.09 r270 bottom value=0.01uF
C111 "GRM1885C1H103JA01D" 0603L 4111,270.2 r90 bottom value=0.01uF
C112 "GRM1885C1H103JA01D" 0603L 4111,375.09 r270 bottom value=0.01uF
C113 "GRM1885C1H103JA01D" 0603L 3911,270.2 r90 bottom value=0.01uF
C114 "GRM1885C1H103JA01D" 0603L 3911,375.09 r270 bottom value=0.01uF
C115 "GRM1885C1H103JA01D" 0603L 3711,270.2 r90 bottom value=0.01uF
C116 "GRM1885C1H103JA01D" 0603L 3711,375.09 r270 bottom value=0.01uF
C117 "GRM32ER71H475KA88L" 1210_270L 692.73,835.88 r180 bottom value=4.7uF
C118 "GRM188R71H683KA93D" 0603L 883.55,4252.66 r180 bottom value=0.068uF
C119 "GRM32ER71H475KA88L" 1210_270L 692.73,715.88 r180 bottom value=4.7uF
C120 "GRM1885C1H271JA01D" 0603L 771.48,4293.5 r180 bottom value=270pF
C121 "GRM188R72A104KA35J" 0603L 1606,370 r270 bottom value=0.1uF
C122 "GRM1885C1H103JA01D" 0603L 1804.28,370 r270 bottom value=0.01uF
C123 "GRM1885C1H271JA01D" 0603L 770.86,4493.19 r0 bottom value=270pF
C124 "GCM188R71E105KA64D" 0603L 611.35,4533.78 r180 top value=1uF
C125 "CMP-0006641-2" 0402L 2348.19,3894.24 r90 bottom value=0.1uF
C126 "GRM32ER71H475KA88L" 1210_270L 470,1320 r90 top value=4.7uF
C127 "GCM188R71E105KA64D" 0603L 745.06,1511.97 r270 bottom value=1uF
C128 "GCM21BR71E225KA73L" 0805L 619.22,4420.32 r180 top value=2.2uF
C129 "CMP-0006641-2" 0402L 2228.22,3894.24 r90 bottom value=0.1uF
C130 "GRM155R71H221KA01D" 0402L 704.85,4564.94 r90 top value=220pF
C131 "UHW1E222MHD" FP-UHW1E222MHD_RADIAL-MFG 2220.3,1721.79 r90 top value=2.2mF
C132 "GCM188R71H224KA64D" 0603L 1197.38,4580.98 r270 top value=0.22uF
C133 "UHW1E222MHD" FP-UHW1E222MHD_RADIAL-MFG 1685.2,1721.79 r90 top value=2.2mF
C134 "GRM188Z71A475ME15D" 0603L 987.25,4532.17 r180 bottom value=4.7uF
C135 "UHW1E222MHD" FP-UHW1E222MHD_RADIAL-MFG 620.79,1721.79 r90 top value=2.2mF
C136 "UHW1E222MHD" FP-UHW1E222MHD_RADIAL-MFG 1151.41,1721.79 r90 top value=2.2mF
C137 "GCM188R71E105KA64D" 0603L 1440.4,4533.78 r180 top value=1uF
C138 "GRM32ER71H106KA12L" 1210_270 1429,2445.33 r180 top locked value=10uF
C139 "GRM32ER71H106KA12L" 1210_270 1430,2592.1 r180 bottom value=10uF
C140 "GRM32ER71H106KA12L" 1210_270 2475.46,2798.66 r180 top value=10uF
C141 "GCM188R71E105KA64D" 0603L 1126.61,4495.39 r0 top value=1uF
C142 "GRM155R71H221KA01D" 0402L 1541.97,4564.94 r90 top value=220pF
C143 "EEE-FT1C470AR" Panasonic_B 2476.89,3406.1 r0 top value=47uF
C144 "GCM188R71H224KA64D" 0603L 2032.19,4580.98 r270 top value=0.22uF
C145 "GRM188Z71A475ME15D" 0603L 1830,4530 r180 bottom value=4.7uF
C146 "GRM32ER71H106KA12L" 1210_270 736.29,2445.33 r180 top locked value=10uF
C147 "GRM32ER71H106KA12L" 1210_270 735.57,2299.9 r180 bottom value=10uF
C148 "GRM32ER71H106KA12L" 1210_270 1430,2299.9 r180 bottom value=10uF
C149 "GRM32ER71H106KA12L" 1210_270 735.57,2446.1 r180 bottom value=10uF
C150 "GRM32ER71H106KA12L" 1210_270 736.29,2300.13 r180 top locked value=10uF
C151 "GRM32ER71H106KA12L" 1210_270 735.57,2592.1 r180 bottom value=10uF
C152 "GRM32ER71H106KA12L" 1210_270 1430,2446.1 r180 bottom value=10uF
C153 "GRM32ER71H106KA12L" 1210_270 1429,2300.13 r180 top locked value=10uF
C154 "GCM1885C2A102JA16D" 0603L 982.73,3104.94 r180 bottom value=1000pF
C155 "GCM1885C2A102JA16D" 0603L 1675.68,3104.94 r180 bottom value=1000pF
C156 "GCM1885C2A102JA16D" 0603L 1267.77,3254.6 r90 bottom value=1000pF
C157 "GCM1885C2A102JA16D" 0603L 1953.98,3251.8 r90 bottom value=1000pF
C158 "GRM188R72A104KA35J" 0603L 793.89,3571.57 r180 top locked value=0.1uF
C159 "GRM188R72A104KA35J" 0603L 1483.84,3571.57 r180 top locked value=0.1uF
C160 "GRM32ER71H106KA12L" 1210_270 1091.86,3713.71 r90 top value=10uF
C161 "GRM32ER71H106KA12L" 1210_270 1641.78,3713.71 r90 top locked value=10uF
C162 "GRM32ER71H106KA12L" 1210_270 954.57,3713.71 r90 top locked value=10uF
C163 "GRM32ER71H106KA12L" 1210_270 1780.95,3713.71 r90 top locked value=10uF
C164 "GRM32ER71H106KA12L" 1210_270 778.09,3666.67 r180 top locked value=10uF
C165 "GRM32ER71H106KA12L" 1210_270 1468.06,3666.67 r180 top locked value=10uF
C166 "GRM188R72A104KA35J" 0603L 1012.86,3945 r180 top locked value=0.1uF
C167 "GRM188R72A104KA35J" 0603L 1012.86,4045 r180 top locked value=0.1uF
C168 "GRM32ER71H106KA12L" 1210_270 973.33,4140 r180 top locked value=10uF
C169 "EMZR500ARA331MJA0G" FP-EMZR500ARA331MJA0G_RADIAL-MFG 2802.91,4461.19 r270 top locked value=330µF
C170 "EMZR500ARA331MJA0G" FP-EMZR500ARA331MJA0G_RADIAL-MFG 2364.56,4461.19 r270 top locked value=330µF
C171 "EMZR500ARA331MJA0G" FP-EMZR500ARA331MJA0G_RADIAL-MFG 3241.2,4461.19 r270 top locked value=330µF
C172 "EMZR500ARA331MJA0G" FP-EMZR500ARA331MJA0G_RADIAL-MFG 4217.88,4461.19 r270 top locked value=330µF
C173 "EMZR500ARA331MJA0G" FP-EMZR500ARA331MJA0G_RADIAL-MFG 3779.54,4461.19 r270 top locked value=330µF
C174 "EMZR500ARA331MJA0G" FP-EMZR500ARA331MJA0G_RADIAL-MFG 4656.22,4461.19 r270 top locked value=330µF
C175 "GRM188Z71A106MA73D" 0603L 6251.46,545 r180 top value=10uF
C176 "GRM188Z71A106MA73D" 0603L 6210,4537.44 r270 bottom value=10uF
C177 "GRM1555C1H200JA01D" 0402L 5982.87,4558 r0 top value=20pF
C178 "CMP-0006408-2" 0402L 6478.62,4435.2 r0 top value=10pF
C179 "CMP-0006641-2" 0402L 6340,4543.94 r90 bottom value=0.1uF
C180 "GRM1555C1H200JA01D" 0402L 5878.9,4558 r180 top value=20pF
C181 "GCM188R71E105KA64D" 0603L 6474.69,4535.59 r0 top value=1uF
C182 "CMP-0006641-2" 0402L 6107.72,4543.94 r90 bottom value=0.1uF
C183 "CMP-0006668-2" 0402L 6225.83,4451.42 r180 bottom value=4700pF
C184 "GRM188R71H683KA93D" 0603L 6217.95,4358.01 r0 bottom value=0.068uF
C185 "CMP-0006408-2" 0402L 6304.08,4238.78 r90 top value=10pF
C186 "CMP-0006408-2" 0402L 6399.8,4238.78 r90 top value=10pF
C187 "GRM1885C1H271JA01D" 0603L 5896.06,305.05 r0 top value=270pF
C188 "CMP-0006408-2" 0402L 6160.51,4238.78 r90 top value=10pF
C189 "GRM1885C1H271JA01D" 0603L 5775.94,305.75 r180 top value=270pF
C190 "GRM1885C1H103JA01D" 0603L 2406,270.56 r90 bottom value=0.01uF
C191 "GRM1885C1H103JA01D" 0603L 2606,270.56 r90 bottom value=0.01uF
C192 "GRM1885C1H103JA01D" 0603L 2406,375.44 r270 bottom value=0.01uF
C193 "GRM1885C1H103JA01D" 0603L 2606,375.44 r270 bottom value=0.01uF
C194 "GRM188Z71A106MA73D" 0603L 5717,4555.24 r270 bottom value=10uF
C195 "GRM188Z71A106MA73D" 0603L 5265.24,4731.47 r0 top value=10uF
C196 "GRM188Z71A106MA73D" 0603L 5265.24,4547.07 r0 top value=10uF
C197 "GRM188Z71A106MA73D" 0603L 5265.24,4670 r0 top value=10uF
C198 "GRM188Z71A106MA73D" 0603L 5265.24,4608.53 r0 top value=10uF
C199 "GRM1555C1H200JA01D" 0402L 5286.78,4409.97 r270 top value=20pF
C200 "GRM1555C1H200JA01D" 0402L 5291.78,4306.97 r90 top value=20pF
C201 "CMP-0006641-2" 0402L 5563.62,4270 r180 top value=0.1uF
C202 "GRM188Z71A106MA73D" 0603L 5571.5,4330 r0 top value=10uF
C203 "GCM188R71E105KA64D" 0603L 5265.99,4489.01 r180 top value=1uF
C204 "GRM188Z71A106MA73D" 0603L 5441.33,4280 r180 top value=10uF
C205 "CMP-0006641-2" 0402L 5449.21,4337.09 r0 top value=0.1uF
C206 "GRM188Z71A106MA73D" 0603L 5498.58,4494.23 r270 bottom value=10uF
C207 "CMP-0006641-2" 0402L 5406.61,4547.87 r270 bottom value=0.1uF
C208 "GRM188Z71A106MA73D" 0603L 5497.8,4045.39 r270 bottom value=10uF
C209 "CMP-0006641-2" 0402L 5587.13,4053.27 r90 bottom value=0.1uF
C210 "GRM188Z71A106MA73D" 0603L 5225.17,230 r180 bottom value=10uF
C211 "GRM188Z71A106MA73D" 0603L 4920.01,244.19 r180 bottom value=10uF
C212 "CMP-0006641-2" 0402L 5233.05,289.5 r0 bottom value=0.1uF
C213 "CMP-0006641-2" 0402L 4927.88,287.19 r0 bottom value=0.1uF
C214 "GRM188Z71A106MA73D" 0603L 5360.46,202.8 r90 bottom value=10uF
C215 "GRM188Z71A106MA73D" 0603L 5059.2,215 r90 bottom value=10uF
C216 "GRM1555C1E120JA01D" 0402L 5657.87,4165 r0 top value=12pF
C217 "GRM1555C1E120JA01D" 0402L 5752.4,4165 r180 top value=12pF
C218 "GCM1885C2A102JA16D" 0603L 5981.55,4076.44 r270 top value=1000pF
C219 "GCM188R71E105KA64D" 0603L 1970.51,4495.19 r0 top value=1uF
C220 "GRM32ER71H106KA12L" 1210_270 1918.05,3713.71 r90 top value=10uF
C221 "GRM32ER71H106KA12L" 1210_270 1229.99,3713.71 r90 top value=10uF
C222 "GRM32ER71H106KA12L" 1210_270 1872.05,3993.68 r0 top value=10uF
C223 "GRM32ER71H106KA12L" 1210_270 753.79,4131.42 r180 top value=10uF
C224 "GRM32ER71H106KA12L" 1210_270 753.3,3986.14 r180 top value=10uF
C225 "GRM32ER71H106KA12L" 1210_270 1647.55,3994.94 r0 top value=10uF
C226 "GRM32ER71H106KA12L" 1210_270 1647.55,4160.34 r0 top value=10uF
C227 "GRM32ER71H106KA12L" 1210_270 1872.05,4149.26 r0 top value=10uF
C228 "CMP-0006641-2" 0402L 5291.98,4085.75 r270 top value=0.1uF
C229 "CMP-0006641-2" 0402L 5291.98,3994.7 r270 top value=0.1uF
C230 "CMP-0006641-2" 0402L 5291.98,3891 r270 top value=0.1uF
D1 "FSV360FP" SOD-123HE 589.36,1191.9 r270 bottom value=60V
D2 "FSV360FP" SOD-123HE 681.25,1192.32 r270 bottom value=60V
D3 "PMEG6010CEH,115" SOD-123F 1164.86,4548.78 r180 bottom value=60V
D4 "PMEG6010CEH,115" SOD-123F 2016.74,4533.78 r180 bottom value=60V
D5 "CMP-0002888-1" LTST-C170KGKT_Green 2428.03,3647.93 r0 top value=Green
D6 "BAT54HT1G" SOD-323 770.54,4112.23 r270 bottom value=30V
D7 "BAT54HT1G" SOD-323 1869.81,4116.62 r270 bottom value=30V
D8 "BAT54HT1G" SOD-323 622.29,4115.4 r270 bottom value=30V
D9 "BAT54HT1G" SOD-323 2018.5,4116.62 r270 bottom value=30V
D10 "FSV360FP" SOD-123HE 1663.36,3430.64 r270 bottom value=60V
D11 "FSV360FP" SOD-123HE 965.06,3430.64 r270 bottom value=60V
D12 "CMP-0002838-1" LED_SMLP12_BLUE 6585.21,4549.69 r180 top value=Blue
D13 "CMP-0002838-1" LED_SMLP12_BLUE 5466.87,4165 r180 top value=Blue
FID1 "DNP" Fiducial6.4-20 6647.8,237.8 r0 top
FID2 "DNP" Fiducial6.4-20 384.88,4731.47 r0 top
FID3 "DNP" Fiducial6.4-20 384.88,237.8 r0 top
FID4 "DNP" Fiducial6.4-20 384.88,237.8 r180 bottom
FID5 "DNP" Fiducial6.4-20 384.88,4731.47 r180 bottom
FID6 "DNP" Fiducial6.4-20 6647.8,237.8 r180 bottom
H1 "Used in BOM report" Heatsink_TAS65xx_EMI 2787,3634 r0 top locked
J1 "1762457" FP-1762457_HDR20-MFG 2506,168.67 r0 top locked
J2 "1736713" FP-1736713_HDR8-MFG 4010.83,168.67 r0 top locked
J3 "61300311021" Wurth_61300311021 5784,130 r0 top locked
J4 "61300311121" WURTH_61300311121 6195,4058 r0 top
J5 "" HARWIN_S1911-46R 3355.75,4120.68 r0 top locked
L1 "BLM18EG601SH1" 0603L 3180.41,3315.53 r90 top value="600 ohm"
L2 "VAMV1009AA-100MM2" FP-VAMV1009AA-100MM2_SMT_CMC_9MM2_10MM2-MFG 4400.13,2250.4 r0 top
L3 "VAMV1009AA-100MM2" FP-VAMV1009AA-100MM2_SMT_CMC_9MM2_10MM2-MFG 3883.27,2250.4 r0 top
L4 "VAMV1009AA-100MM2" FP-VAMV1009AA-100MM2_SMT_CMC_9MM2_10MM2-MFG 3366.41,2250.4 r0 top
L5 "VAMV1009AA-100MM2" FP-VAMV1009AA-100MM2_SMT_CMC_9MM2_10MM2-MFG 2849.55,2250.4 r0 top
L6 "VAMV1009AA-100MM2" FP-VAMV1009AA-100MM2_SMT_CMC_9MM2_10MM2-MFG 6467.57,2250.4 r0 top
L7 "VAMV1009AA-100MM2" FP-VAMV1009AA-100MM2_SMT_CMC_9MM2_10MM2-MFG 5950.71,2250.4 r0 top
L8 "VAMV1009AA-100MM2" FP-VAMV1009AA-100MM2_SMT_CMC_9MM2_10MM2-MFG 5433.85,2250.4 r0 top
L9 "VAMV1009AA-100MM2" FP-VAMV1009AA-100MM2_SMT_CMC_9MM2_10MM2-MFG 4916.99,2250.4 r0 top
L10 "SRP1265A-1R0M" SRP1265a 671,910 r180 top value=1uH
L11 "BLM18EG601SH1" 0603L 2476.89,2690.51 r0 top value="600 ohm"
L12 "SRP1770TA-4R7M" SRP1770TA 998.21,2897.57 r90 top locked value=4.7uH
L13 "SRP1770TA-4R7M" SRP1770TA 1690.91,2897.57 r90 top locked value=4.7uH
L14 "SRP7030-R20FM" SRP7030F_3 1388.84,4036.33 r90 top locked value=200nH
L15 "BLM18EG601SH1" 0603L 6053.36,4573.62 r90 bottom value="600 ohm"
L16 "BLM18EG601SH1" 0603L 5657.15,4555.24 r270 bottom value="600 ohm"
L17 "BLM18EG601SH1" 0603L 5400.74,4072.95 r180 bottom value="600 ohm"
L18 "BLM18EG601SH1" 0603L 5280.29,175 r180 bottom value="600 ohm"
L19 "BLM18EG601SH1" 0603L 4974.2,190 r180 bottom value="600 ohm"
Logo1 "Texas Instruments" TI_Stacked_Overlay_Small 2660,4080 r0 top locked
Logo2 "FCC disclaimer" FCC_disclaimer_stacked 5011.65,740.46 r0 top locked
Logo3 "WEEE logo" WEEE_Minimum 6049.25,855.67 r0 top locked
Logo4 "CE Mark" CE_Mark_5mm 5648.8,782.18 r0 top locked
MP1 "3670378" FP-3670378_RF_SHIELD-MFG 1315,3278.71 r180 bottom locked
MP2 "3670548" FP-3670548_RF_SHIELD-MFG 1312.68,3209.52 r90 top locked
Q1 "CSD16570Q5B" DNK0008A#1 823.3,1317.44 r90 top value=25V
Q2 "CSD18540Q5B" DNK0008A#2 796.67,3399.8 r0 top locked value=60V
Q3 "CSD18540Q5B" DNK0008A#2 1487.03,3399.8 r0 top locked value=60V
Q4 "CSD18540Q5B" DNK0008A#2 1087.83,3449 r90 top locked value=60V
Q5 "CSD18540Q5B" DNK0008A#2 1784.32,3449 r90 top locked value=60V
Q6 "MMBT3906" SOT-23 6612.24,4662.6 r0 top value="40 V"
R1 "CRCW04022K20FKED" 0402L 3575.2,3591.79 r90 bottom value=2.20k
R2 "CMP-0025958-3" 0402L 3814.21,3591.79 r90 top value=10.0k
R3 "CRCW04022K20FKED" 0402L 3626.19,3591.79 r90 bottom value=2.20k
R4 "CMP-0025958-3" 0402L 4191,3259.09 r0 top value=10.0k
R5 "CRCW04022K20FKED" 0402L 3770.9,3591.79 r90 top value=2.20k
R6 "CMP-0025958-3" 0402L 4191,3303.09 r0 top value=10.0k
R7 "CMP-0025958-3" 0402L 4191,3347.08 r0 top value=10.0k
R8 "DNP" 0402L 3727.6,3591.79 r90 top value=0
R9 "CRCW04020000Z0ED" 0402L 3684.29,3591.79 r90 top value=0
R10 "CMP-0025958-3" 0402L 4256.45,3280.43 r90 top value=10.0k
R11 "CMP-0025958-3" 0402L 3727.65,3394.8 r180 bottom value=10.0k
R12 "CRCW04020000Z0ED" 0402L 3987.59,3425.59 r90 bottom value=0
R13 "DNP" 0402L 4292.95,3280.43 r270 top value=10.0k
R14 "CRCW04020000Z0ED" 0402L 3996.91,3595.05 r90 top value=0
R15 "CRCW04020000Z0ED" 0402L 4042.64,3514.17 r90 top value=0
R16 "CRCW080510R0JNEA" 0805_HV 4071.43,3063.96 r270 bottom value=10
R17 "CRCW080510R0JNEA" 0805_HV 4245.26,3033.93 r90 bottom value=10
R18 "CRCW080510R0JNEA" 0805_HV 4034.43,2678.61 r180 bottom value=10
R19 "CRCW080510R0JNEA" 0805_HV 3837.8,2775.57 r270 bottom value=10
R20 "CRCW080510R0JNEA" 0805_HV 3697.48,2775.57 r270 bottom value=10
R21 "CRCW080510R0JNEA" 0805_HV 3388.73,2690.98 r180 bottom value=10
R22 "CRCW080510R0JNEA" 0805_HV 3261.39,3022.48 r90 bottom value=10
R23 "CRCW080510R0JNEA" 0805_HV 3381.14,3128.3 r180 bottom value=10
R24 "MCR25JZHJ000" 1210 4580.85,1765.95 r270 top value=0
R25 "MCR25JZHJ000" 1210 4215.96,1765.95 r270 top value=0
R26 "MCR25JZHJ000" 1210 4064.01,1765.95 r270 top value=0
R27 "MCR25JZHJ000" 1210 3699.12,1765.95 r270 top value=0
R28 "MCR25JZHJ000" 1210 3547.17,1765.95 r270 top value=0
R29 "MCR25JZHJ000" 1210 3182.28,1765.95 r270 top value=0
R30 "MCR25JZHJ000" 1210 3030.33,1765.95 r270 top value=0
R31 "MCR25JZHJ000" 1210 2665.44,1765.95 r270 top value=0
R32 "CMP-0025958-3" 0402L 5881.57,3591.79 r90 top value=10.0k
R33 "CMP-0025958-3" 0402L 6258.14,3259.09 r0 top value=10.0k
R34 "CRCW080510R0JNEA" 0805_HV 5938.99,3235.16 r180 bottom value=10
R35 "CMP-0025958-3" 0402L 6258.14,3304.14 r0 top value=10.0k
R36 "CMP-0025958-3" 0402L 6258.14,3346.73 r0 top value=10.0k
R37 "CRCW04020000Z0ED" 0402L 5795.93,3591.79 r90 top value=0
R38 "DNP" 0402L 5753.11,3591.79 r90 top value=0
R39 "CMP-0025958-3" 0402L 6319.53,3322.68 r90 top value=10.0k
R40 "CMP-0025958-3" 0402L 5794.89,3390.15 r180 bottom value=10.0k
R41 "CRCW04020000Z0ED" 0402L 6054.6,3427.08 r90 bottom value=0
R42 "DNP" 0402L 6351.02,3322.68 r270 top value=10.0k
R43 "CRCW04020000Z0ED" 0402L 6063.61,3596.55 r90 top value=0
R44 "CRCW04020000Z0ED" 0402L 6112.16,3515.67 r90 top value=0
R45 "CRCW080510R0JNEA" 0805_HV 6315.93,2823.48 r270 bottom value=10
R46 "CRCW080510R0JNEA" 0805_HV 6096.66,2675.17 r180 bottom value=10
R47 "CRCW080510R0JNEA" 0805_HV 5904.54,2771.1 r270 bottom value=10
R48 "CRCW080510R0JNEA" 0805_HV 5765.48,2771.1 r270 bottom value=10
R49 "CRCW080510R0JNEA" 0805_HV 5452.65,2683.98 r180 bottom value=10
R50 "CRCW080510R0JNEA" 0805_HV 5329.9,3026.55 r90 bottom value=10
R51 "CRCW080510R0JNEA" 0805_HV 5445.51,3127.2 r180 bottom value=10
R52 "CMP-0025958-3" 0402L 5252.91,4085.75 r90 top value=10.0k
R53 "MCR25JZHJ000" 1210 6638.2,1765.95 r270 top value=0
R54 "MCR25JZHJ000" 1210 6283.31,1765.95 r270 top value=0
R55 "MCR25JZHJ000" 1210 6131.37,1765.95 r270 top value=0
R56 "MCR25JZHJ000" 1210 5766.47,1765.95 r270 top value=0
R57 "MCR25JZHJ000" 1210 5614.53,1765.95 r270 top value=0
R58 "MCR25JZHJ000" 1210 5249.64,1765.95 r270 top value=0
R59 "MCR25JZHJ000" 1210 5097.69,1765.95 r270 top value=0
R60 "MCR25JZHJ000" 1210 4732.8,1765.95 r270 top value=0
R61 "CRCW0402100KFKED" 0402L 759.67,4343 r180 bottom value=100k
R62 "CRCW040268K1FKED" 0402L 759.67,4245.77 r0 bottom value=68.1k
R63 "CRCW04023K57FKED" 0402L 656.99,4343 r0 bottom value=3.57k
R64 "CRCW0402750RFKED" 0402L 2408.08,3915.9 r180 bottom value=750
R65 "CMP-0025958-3" 0402L 5252.91,3994.7 r90 top value=10.0k
R66 "CMP-0025958-3" 0402L 5252.91,3891 r90 top value=10.0k
R67 "0ohm" 0402L 1114.8,4437.38 r180 top value=0
R69 "CRCW040230K1FKED" 0402L 617.54,4484 r180 top value=30.1k
R70 "CRCW04027K68FKED" 0402L 762.99,4445.69 r180 bottom value=7.68k
R71 "CRCW06033R30JNEA" 0603L 611.35,4594.44 r180 top value=3.3
R72 "CRCW0402750RFKED" 0402L 2287.97,3915.9 r180 bottom value=750
R73 "CRCW040220K0FKED" 0402L 1114.6,4388.22 r180 top value=20.0k
R74 "CRCW040220K0FKED" 0402L 761.89,4403.81 r180 bottom value=20.0k
R75 "CMP-0025958-3" 0402L 884.78,4343.82 r0 bottom value=10.0k
R76 "CRCW04020000Z0ED" 0402L 1116.71,4608.54 r180 top value=0
R77 "CRCW04020000Z0ED" 0402L 1115.47,4557.16 r180 top value=0
R80 "0" 0402L 1958.7,4437.38 r180 top
R81 "CRCW06033R30JNEA" 0603L 1440.4,4594.44 r180 top value=3.3
R82 "CRCW040220K0FKED" 0402L 1958.7,4388.22 r180 top value=20.0k
R83 "CRCW04020000Z0ED" 0402L 1958.7,4608.54 r180 top value=0
R84 "CRCW04020000Z0ED" 0402L 1958.7,4556.77 r180 top value=0
R86 "CRCW04021K00JNED" 0402L 2560.18,3647.93 r90 top value=1.0k
R87 "CRCW04021K00JNED" 0402L 1079.64,2267.44 r0 bottom value=1.0k
R88 "CRCW04021K00JNED" 0402L 1773.92,2264.6 r0 bottom value=1.0k
R89 "PA2512FKF070R003E" PA2512 1031.82,2390 r0 top locked value=0.003
R90 "PA2512FKF070R003E" PA2512 1726.5,2390 r0 top locked value=0.003
R91 "CRCW04021K00JNED" 0402L 1143.38,2334.12 r180 bottom value=1.0k
R92 "CRCW04021K00JNED" 0402L 1837.75,2337.36 r180 bottom value=1.0k
R93 "CRCW20108R20JNEF" 2010 787.59,3069 r0 bottom value=8.2
R94 "CRCW20108R20JNEF" 2010 1470.55,3069 r0 bottom value=8.2
R95 "CRCW06032R00JNEA" 0603 700.1,4129.83 r270 bottom value=2.0
R96 "CRCW06032R00JNEA" 0603 1940.92,4134.14 r270 bottom value=2.0
R97 "CRCW06032R00JNEA" 0603 551.87,4132.92 r270 bottom value=2.0
R98 "CRCW06032R00JNEA" 0603 2089.62,4134.14 r270 bottom value=2.0
R99 "CRCW20108R20JNEF" 2010 1241,3449 r90 bottom value=8.2
R100 "CRCW20108R20JNEF" 2010 1915.45,3443 r90 bottom value=8.2
R101 "ERJ-1TRQJR68U" 2512 1165.94,4056.3 r90 top locked value=0.68
R102 "CRCW251210K0FKEG" 2512 2869,3807.86 r270 bottom value=10.0k
R103 "MCR25JZHJ000" 1210 4154.99,4119.52 r180 top locked value=0
R104 "MCR25JZHJ000" 1210 3716.55,4119.52 r180 top locked value=0
R105 "MCR25JZHJ000" 1210 4592.73,4119.52 r180 top locked value=0
R106 "CMP-0026404-2" 0402L 6478.62,4384.02 r180 top value=49.9
R107 "CMP-0025950-3" 0402L 6474.69,4486.81 r0 top value=100k
R108 "DNP" 0402L 5980,4436.19 r180 top value=4.99k
R109 "CMP-0026414-2" 0402L 5980,4295 r180 top value=4.99k
R110 "CRCW0402470RJNED" 0402L 5969,4494 r0 top value=470
R111 "CMP-0026414-2" 0402L 6478.62,4585 r0 top value=4.99k
R112 "CMP-0026414-2" 0402L 5980,4388.19 r0 top value=4.99k
R113 "DNP" 0402L 5980,4343 r0 top value=4.99k
R114 "CMP-0026404-2" 0402L 6450,4660 r270 top value=49.9
R115 "CMP-0026404-2" 0402L 6256.22,4238.78 r270 top value=49.9
R116 "CMP-0026404-2" 0402L 6351.94,4238.78 r270 top value=49.9
R117 "CMP-0026404-2" 0402L 6208.37,4238.78 r270 top value=49.9
R118 "CMP-0026505-2" 0402L 6225.83,4406.01 r0 bottom value=681
R119 "CMP-0026414-2" 0402L 6500.28,4660 r270 top value=4.99k
R120 "CRCW06034K70JNEA" 0603L 5896.06,505.12 r0 top value=4.7k
R121 "CRCW06034K70JNEA" 0603L 5775.94,505.12 r180 top value=4.7k
R122 "CMP-0026404-2" 0402L 5803.5,403.28 r270 top value=49.9
R123 "CMP-0026404-2" 0402L 5868.5,403.28 r270 top value=49.9
R124 "CRCW04021K00JNED" 0402L 6591.12,4502.44 r0 top value=1.0k
R125 "CRCW04020000Z0ED" 0402L 5983.94,4215.16 r0 top value=0
R126 "CRCW04020000Z0ED" 0402L 6112.65,4238.78 r270 top value=0
R127 "CMP-0025958-3" 0402L 6668,4526.07 r90 top value=10.0k
R128 "CMP-0025958-3" 0402L 2387.8,727.8 r270 top value=10.0k
R129 "CMP-0025958-3" 0402L 2498.8,727.8 r270 top value=10.0k
R130 "CMP-0025958-3" 0402L 2427.8,727.8 r270 top value=10.0k
R131 "CMP-0025958-3" 0402L 2539.21,727.8 r270 top value=10.0k
R132 "CMP-0025958-3" 0402L 5146.36,4731.47 r0 top value=10.0k
R133 "CMP-0025958-3" 0402L 5146.36,4547.07 r0 top value=10.0k
R134 "CMP-0025958-3" 0402L 5146.36,4670 r0 top value=10.0k
R135 "CMP-0025958-3" 0402L 5146.36,4608.53 r0 top value=10.0k
R136 "CRCW04021K00JNED" 0402L 5751.02,4555.24 r180 top value=1.0k
R137 "CRCW04021K00JNED" 0402L 5751.02,4602.95 r180 top value=1.0k
R138 "CRCW06033R30JNEA" 0603L 5441.33,4226.25 r180 top value=3.3
R139 "DNP" 0402L 5751.02,4507.52 r180 top value=0
R140 "DNP" 0402L 5751.02,4412.1 r180 top value=0
R141 "DNP" 0402L 5751.02,4459.81 r180 top value=0
R142 "CRCW06033R30JNEA" 0603L 5526.14,4584.29 r0 bottom value=3.3
R143 "CRCW04021K00JNED" 0402L 5549.88,4165 r180 top value=1.0k
R144 "CRCW04020000Z0ED" 0402L 5848.38,3966.33 r0 top value=0
R145 "CRCW04020000Z0ED" 0402L 5848.38,4014.22 r0 top value=0
R146 "CRCW04020000Z0ED" 0402L 5424.68,3886.53 r180 top value=0
R147 "CRCW04020000Z0ED" 0402L 5424.68,3956.22 r180 top value=0
R148 "DNP" 0402L 5583.77,3795 r270 top value=0
R149 "CRCW04020000Z0ED" 0402L 5680.54,3795 r270 top value=0
R150 "DNP" 0402L 5843.38,3822.65 r0 top value=0
R151 "CRCW04020000Z0ED" 0402L 5848.38,3918.44 r0 top value=0
R152 "CRCW04020000Z0ED" 0402L 5484.53,4079.63 r90 top value=0
R153 "CRCW04020000Z0ED" 0402L 5449.53,4079.63 r90 top value=0
R154 "CRCW04020000Z0ED" 0402L 4797.63,259.96 r270 bottom value=0
R155 "CMP-0025958-3" 0402L 5433.57,268.53 r180 bottom value=10.0k
R156 "CRCW06034K70JNEA" 0603L 4736.22,252.09 r90 bottom value=4.7k
R157 "CMP-0025958-3" 0402L 5843.38,3966.33 r0 bottom value=10.0k
R158 "CRCW04020000Z0ED" 0402L 5487,3795 r90 top value=0
R159 "CRCW04020000Z0ED" 0402L 5535.38,3795 r90 top value=0
R160 "CMP-0025958-3" 0402L 5843.38,4014.22 r0 bottom value=10.0k
R161 "CRCW040247K0JNED" 0402L 5933.65,4084.31 r270 top value=47k
RT1 "NCP18XH103D03RB" 0603S 673.84,3267.34 r180 top value=10k
RT2 "NCP18XH103D03RB" 0603S 1322.47,3335.01 r270 top value=10k
RT3 "NCP18XH103D03RB" 0603S 2650.55,4717 r180 top value=10k
U1 "TAS6584Q1PHD" QFP64-PHD 3765,3150 r270 top locked
U2 "TAS6584Q1PHD" QFP64-PHD 5832.36,3150 r270 top locked
U3 "LM74700QDBVTQ1" DBV0006A_N 877.44,1517.81 r0 bottom
U4 "LM5122MHX/NOPB" PWP0020A_N 878.03,4493.38 r0 top locked
U5 "LM5122MHX/NOPB" PWP0020A_N 1721.65,4492.99 r0 top locked
U6 "LM1117IDT-3.3/NOPB" NDP0003B_N 2476.89,3090.68 r90 top
U7 "CMP-0004896-1" PLR135_T10 6262.9,212 r180 top locked
U8 "TI-DIR9001-Q1-TSSOP_PW-28" PW0028A_N 6223.86,4503.58 r0 top
U9 "PCM1863DBT" DBT0030A_N 5522.76,4540 r0 top locked
U10 "MSP430G2553IRHB32R" RHB0032E 5622.71,3985.75 r0 top
U11 "AFBR-2624Z" FP-AFBR-2624Z_PTH_RX_12MM2_18MM8-MFG 5320.53,129.61 r0 top locked
U12 "AFBR-1624Z" FP-AFBR-1624Z_PTH_TX_18MM8_12MM2-MFG 4915.35,129.41 r0 top locked
Y1 "ABM10-24.576MHZ-E20-T" XTAL_ABM10 5935,4638.5 r90 top
Y2 "ABM10-24.576MHZ-E20-T" XTAL_ABM10 5207.55,4357.2 r0 top
Y3 "ECS-.327-12.5-34B-TR" ECS_ECX_31B 5710.63,4242.13 r180 top

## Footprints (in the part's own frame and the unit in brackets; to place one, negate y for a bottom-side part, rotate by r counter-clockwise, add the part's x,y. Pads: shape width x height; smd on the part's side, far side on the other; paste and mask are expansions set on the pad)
0402L [mm] "0402 from SM-752 data"
  rect 0.6x0.5 smd: 1(-0.5,0) 2(0.5,0)
  body extent -0.55,-0.3 0.55,0.3, height 0.6
0603 [mm] "0603 from SM-752 data"
  rect 1x0.95 smd: 1(-0.8,0) 2(0.8,0)
  silkscreen extent -1.52,-0.69 1.52,0.69, body extent -0.87,-0.47 0.87,0.47, height 1
0603L [mm] "0603 from SM-752 data"
  rect 0.8x0.85 smd: 1(-0.7,0) 2(0.7,0)
  silkscreen extent -0.07,-0.33 0.07,0.33, body extent -0.87,-0.47 0.87,0.47, height 1
0603S [mil]
  rect 20x35 smd: 1(-30,0) 2(30,0)
  body extent -34,-19 34,19, height 39
0805_HV [mil] "0805 with 30mil clearance between pads"
  rect 50x63 smd: 1(-40,0) 2(40,0)
  silkscreen extent -74,-40 74,40, body extent -43,-29 43,29, height 57
0805L [mm] "0805 from SM-752 data"
  rect 1.1x1.4 smd: 1(-0.75,0) 2(0.75,0)
  body extent -1.1,-0.72 1.1,0.72, height 1.45
1206L [mm] "1206 from SM-752 data"
  rect 1.1x1.75 smd: 1(-1.35,0) 2(1.35,0)
  silkscreen extent -0.4,-0.77 0.4,0.77, body extent -1.7,-0.9 1.7,0.9, height 1.35
1210 [mm] "1210 from SM-752 data"
  rect 1.3x2.7 smd: 1(-1.45,0) 2(1.45,0)
  silkscreen extent -2.32,-1.57 2.32,1.57, body extent -1.7,-1.35 1.7,1.35, height 1.35
1210_270 [mm] "1210"
  rect 1.3x2.7 smd: 1(-1.45,0) 2(1.45,0)
  silkscreen extent -2.32,-1.57 2.32,1.57, body extent -1.7,-1.35 1.7,1.35, height 2.7
1210_270L [mm] "1210"
  rect 1.1x2.6 smd: 1(-1.35,0) 2(1.35,0)
  silkscreen extent -0.4,-1.2 0.4,1.2, body extent -1.7,-1.35 1.7,1.35, height 2.7
2010 [mm] "Chip Capacitor, Body 5.08x2.54mm, IPC Medium Density"
  rect 1.6x2.7 smd: 1(-2.3,0) 2(2.3,0)
  silkscreen extent -3.42,-1.65 3.42,1.65, body extent -2.73,-1.45 2.73,1.45, height 1.66
2512 [mm] "Chip Resistor, Body 6.3x3.2mm, IPC Medium Density"
  rect 1.3x3.4 smd: 1(-2.95,0) 2(2.95,0)
  silkscreen extent -1.9,-1.6 1.9,1.6, body extent -3.22,-1.67 3.22,1.67, height 0.71
CE_Mark_5mm [mil] "Minimum text height for CE Mark"
  silkscreen extent -138,-98 138,98
DBT0030A_N [mm] "TSSOP, 30-Leads, Body 7.8x4.4mm, Pitch 0.5mm, IPC Medium Density"
  oval 1.4x0.3 smd: 1(-2.95,3.5) 2(-2.95,3) 3(-2.95,2.5) 4(-2.95,2) 5(-2.95,1.5) 6(-2.95,1) 7(-2.95,0.5) 8(-2.95,0) 9(-2.95,-0.5) 10(-2.95,-1) 11(-2.95,-1.5) 12(-2.95,-2) 13(-2.95,-2.5) 14(-2.95,-3) 15(-2.95,-3.5) 16(2.95,-3.5) 17(2.95,-3) 18(2.95,-2.5) 19(2.95,-2) 20(2.95,-1.5) 21(2.95,-1) 22(2.95,-0.5) 23(2.95,0) 24(2.95,0.5) 25(2.95,1) 26(2.95,1.5) 27(2.95,2) 28(2.95,2.5) 29(2.95,3) 30(2.95,3.5)
  silkscreen extent -3.42,-3.95 1.5,3.95, body extent -3.21,-3.9 3.21,3.9, height 1.2
DBV0006A_N [mm] "SOT23, 6-Leads, Body 2.9x1.6mm, Pitch 0.95mm, Lead Span 2.8mm, IPC Medium Density"
  rrect17% 1x0.6 smd: 1(-1.375,0.95) 2(-1.375,0) 3(-1.375,-0.95) 4(1.375,-0.95) 5(1.375,0) 6(1.375,0.95)
  silkscreen extent -1.68,-1.55 0.5,1.55, body extent -1.42,-1.46 1.42,1.46, height 1.12
DNK0008A#1 [mm] "SON, 8-Leads, Body 5x6mm"
  rrect39% 0.86x0.51 smd paste-0.05 mask-0.05: 1(-2.82,1.905) 2(-2.82,0.635) 3(-2.82,-0.635) 4(-2.82,-1.905) 5(2.82,-1.905) 6(2.82,-0.635) 7(2.82,0.635) 8(2.82,1.905)
  rrect8% 1.48x1.27 on Top Paste: 9(-0.18,1.47) 9(-0.18,0) 9(-0.18,-1.47) 9(1.5,-1.47) 9(1.5,0) 9(1.5,1.47)
  rrect5% 4.34x4.6 smd paste-3 mask-0.05: 9(1.08,0)
  silkscreen extent -3.2,-2.7 3.2,2.7, body extent -3.05,-2.55 3.05,2.55, height 1.06
DNK0008A#2 [mm] "SON, 8-Leads, Body 5x6mm"
  rrect39% 0.86x0.51 smd paste-0.05 mask-0.05: 1(-2.82,1.905) 2(-2.82,0.635) 3(-2.82,-0.635) 4(-2.82,-1.905) 5(2.82,-1.905) 6(2.82,-0.635) 7(2.82,0.635) 8(2.82,1.905)
  rrect40% 0.25x0.555 on Top Paste: 9(-0.83,-2.372) 9(-0.83,2.372)
  rrect40% 0.25x0.555 on Top Solder: 9(-0.83,-2.372) 9(-0.83,2.372)
  rrect11% 0.95x1.13 on Top Paste: 9(-0.535,-1.33) 9(-0.535,0) 9(-0.535,1.33) 9(0.615,-1.33) 9(0.615,0) 9(0.615,1.33) 9(1.765,-1.33) 9(1.765,0) 9(1.765,1.33)
  rrect3% 3.58x4 on Top Solder: 9(0.75,0)
  rrect5% 4.34x5.4 smd paste-3 mask-3: 9(1.08,0)
  body extent -3.05,-2.55 3.05,2.55, height 1.06
ECS_ECX_31B [mm] "SMD, 2-Leads, Body 3.2x1.5mm"
  rrect9% 1.1x1.9 smd: 1(-1.25,0) 2(1.25,0)
  body extent -1.6,-0.75 1.6,0.75, height 0.9
FCC_disclaimer_stacked [mil]
Fiducial6.4-20 [mil]
  round 25 smd mask+26.87: 1(0,0)
  Top Layer keep-out circle w46.37: c0,0 r19.68
FP-1736713_HDR8-MFG [mm]
  rrect5% 2.15x2.15 hole 1.4 paste-1000 mask+0: 1(-7.62,9)
  round 2.15 hole 1.4 paste-1000 mask+0: 2(-7.62,-1.16) 3(-2.54,9) 4(-2.54,-1.16) 5(2.54,9) 6(2.54,-1.16) 7(7.62,9) 8(7.62,-1.16)
  silkscreen extent -11.76,-11.1 11.04,11.1, body extent -11.14,-11.2 11.14,11.2, height 0.25
FP-1762457_HDR20-MFG [mm]
  rrect5% 2.15x2.15 hole 1.4 paste-1000 mask+0: 1(-22.86,9)
  round 2.15 hole 1.4 paste-1000 mask+0: 2(-22.86,-1.16) 3(-17.78,9) 4(-17.78,-1.16) 5(-12.7,9) 6(-12.7,-1.16) 7(-7.62,9) 8(-7.62,-1.16) 9(-2.54,9) 10(-2.54,-1.16) 11(2.54,9) 12(2.54,-1.16) 13(7.62,9) 14(7.62,-1.16) 15(12.7,9) 16(12.7,-1.16) 17(17.78,9) 18(17.78,-1.16) 19(22.86,9) 20(22.86,-1.16)
  body extent -26.4,-11.2 26.4,11.2, height 0.25
FP-3670378_RF_SHIELD-MFG [mm]
  round 1.5 smd paste-1000 mask-1000: 1(0,10.65)
  Top Layer lines w1.5: 18.75,-8.25 cw(c16.35,-8.25) 16.35,-10.65 -16.35,-10.65 cw(c-16.35,-8.25) -18.75,-8.25 -18.75,8.25 cw(c-16.35,8.25) -16.35,10.65 16.35,10.65 cw(c16.35,8.25) 18.75,8.25 18.75,-8.25
  silkscreen extent -19.87,-11.78 19.87,11.78, body extent -18.9,-10.8 18.9,10.8, height 3.2
FP-3670548_RF_SHIELD-MFG [mm]
  round 1.5 smd paste-1000 mask-1000: 1(0,20.15)
  Top Layer lines w1.5: -23.15,20.15 ccw(c-23.15,16.15) -27.15,16.15 -27.15,-16.15 ccw(c-23.15,-16.15) -23.15,-20.15 23.15,-20.15 ccw(c23.15,-16.15) 27.15,-16.15 27.15,16.15 ccw(c23.15,16.15) 23.15,20.15 -23.15,20.15
  silkscreen extent -28.4,-21.4 28.4,21.4, body extent -28,-21 28,21, height 0.25
FP-AFBR-1624Z_PTH_TX_18MM8_12MM2-MFG [mm]
  rrect6% 1.55x1.55 hole 1 paste-1000 mask+0: 1(2.81,6.6)
  round 1.55 hole 1 paste-1000 mask+0: 3(-2.27,6.6) 4(-4.81,6.6) 5(-4.81,-1.1) 8(2.81,-1.1)
  silkscreen extent -6.1,-2.5 6.83,9.4, body extent -6.2,-9.5 6.2,9.5, height 0.25
FP-AFBR-2624Z_PTH_RX_12MM2_18MM8-MFG [mm]
  rrect6% 1.55x1.55 hole 1 paste-1000 mask+0: 1(2.81,6.6)
  round 1.55 hole 1 paste-1000 mask+0: 2(0.27,6.6) 3(-2.27,6.6) 4(-4.81,6.6) 5(-4.81,-1.1) 8(2.81,-1.1)
  silkscreen extent -6.1,-2 6.1,10.12, body extent -6.2,-9.5 6.2,9.5, height 0.25
FP-EMZR500ARA331MJA0G_RADIAL-MFG [mm]
  rrect5% 4.4x2.2 smd paste+0 mask+0: 1(-4.45,0) 2(4.45,0)
  silkscreen extent -7.35,-5.25 5.25,5.25, body extent -6.9,-5.5 6.9,5.5, height 0.25
FP-UHW1E222MHD_RADIAL-MFG [mm]
  rrect8% 1.25x1.25 hole 0.75 paste-1000 mask+0: 1(-2.5,0)
  round 1.25 hole 0.75 paste-1000 mask+0: 2(2.5,0)
  silkscreen extent -6.5,-6.5 6.5,6.5, body extent -6.6,-6.6 6.6,6.6, height 0.25
FP-VAMV1009AA-100MM2_SMT_CMC_9MM2_10MM2-MFG [mm]
  rrect4% 4.05x2.85 smd paste+0 mask+0: 1(-3.945,2.475) 2(-3.945,-2.475) 3(3.945,-2.475) 4(3.945,2.475)
  silkscreen extent -6.65,-5.2 4.7,5.2, body extent -6.07,-5.3 6.07,5.3, height 0.25
HARWIN_S1911-46R [mm] "HARWIN"
  rect 2.48x3 smd mask+0.102: 1(-2.69,0) 2(2.69,0)
  silkscreen extent -0.5,-1.5 0.5,1.5, body extent -3.42,-1.25 3.43,1.26, height 0.99
Heatsink_TAS65xx_EMI [mm]
  round 6 hole 4: 1(7.01,-12.497) 2(93.015,-12.497)
  silkscreen extent 0,-24.99 100,0
LED_SMLP12_BLUE [mm] "Rohm Semiconductor"
  rect 0.5x0.6 smd mask+0.08: 1(-0.45,0) 2(0.45,0)
  silkscreen extent 0.92,-0.3 0.92,0.3, body extent -0.55,-0.35 0.55,0.35, height 0.25
LTST-C170KGKT_Green [mm] "LITE-ON"
  rect 1.2x1.2 smd: 1(-1.05,0) 2(1.05,0)
  silkscreen extent -1.6,-1 2.2,1, body extent -1.05,-0.67 1.05,0.67, height 1.1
